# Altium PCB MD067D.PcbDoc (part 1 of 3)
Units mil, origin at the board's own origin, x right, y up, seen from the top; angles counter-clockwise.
Board outline 3650 x 4750 mil, 4 copper layers (Top Layer, GND Layer, Power Layer, Bottom Layer), stack 58.4 mil thick; 234 components, 118 nets, 588 pads, 975 vias.
Unrouted connection lines stored in the file: 45.
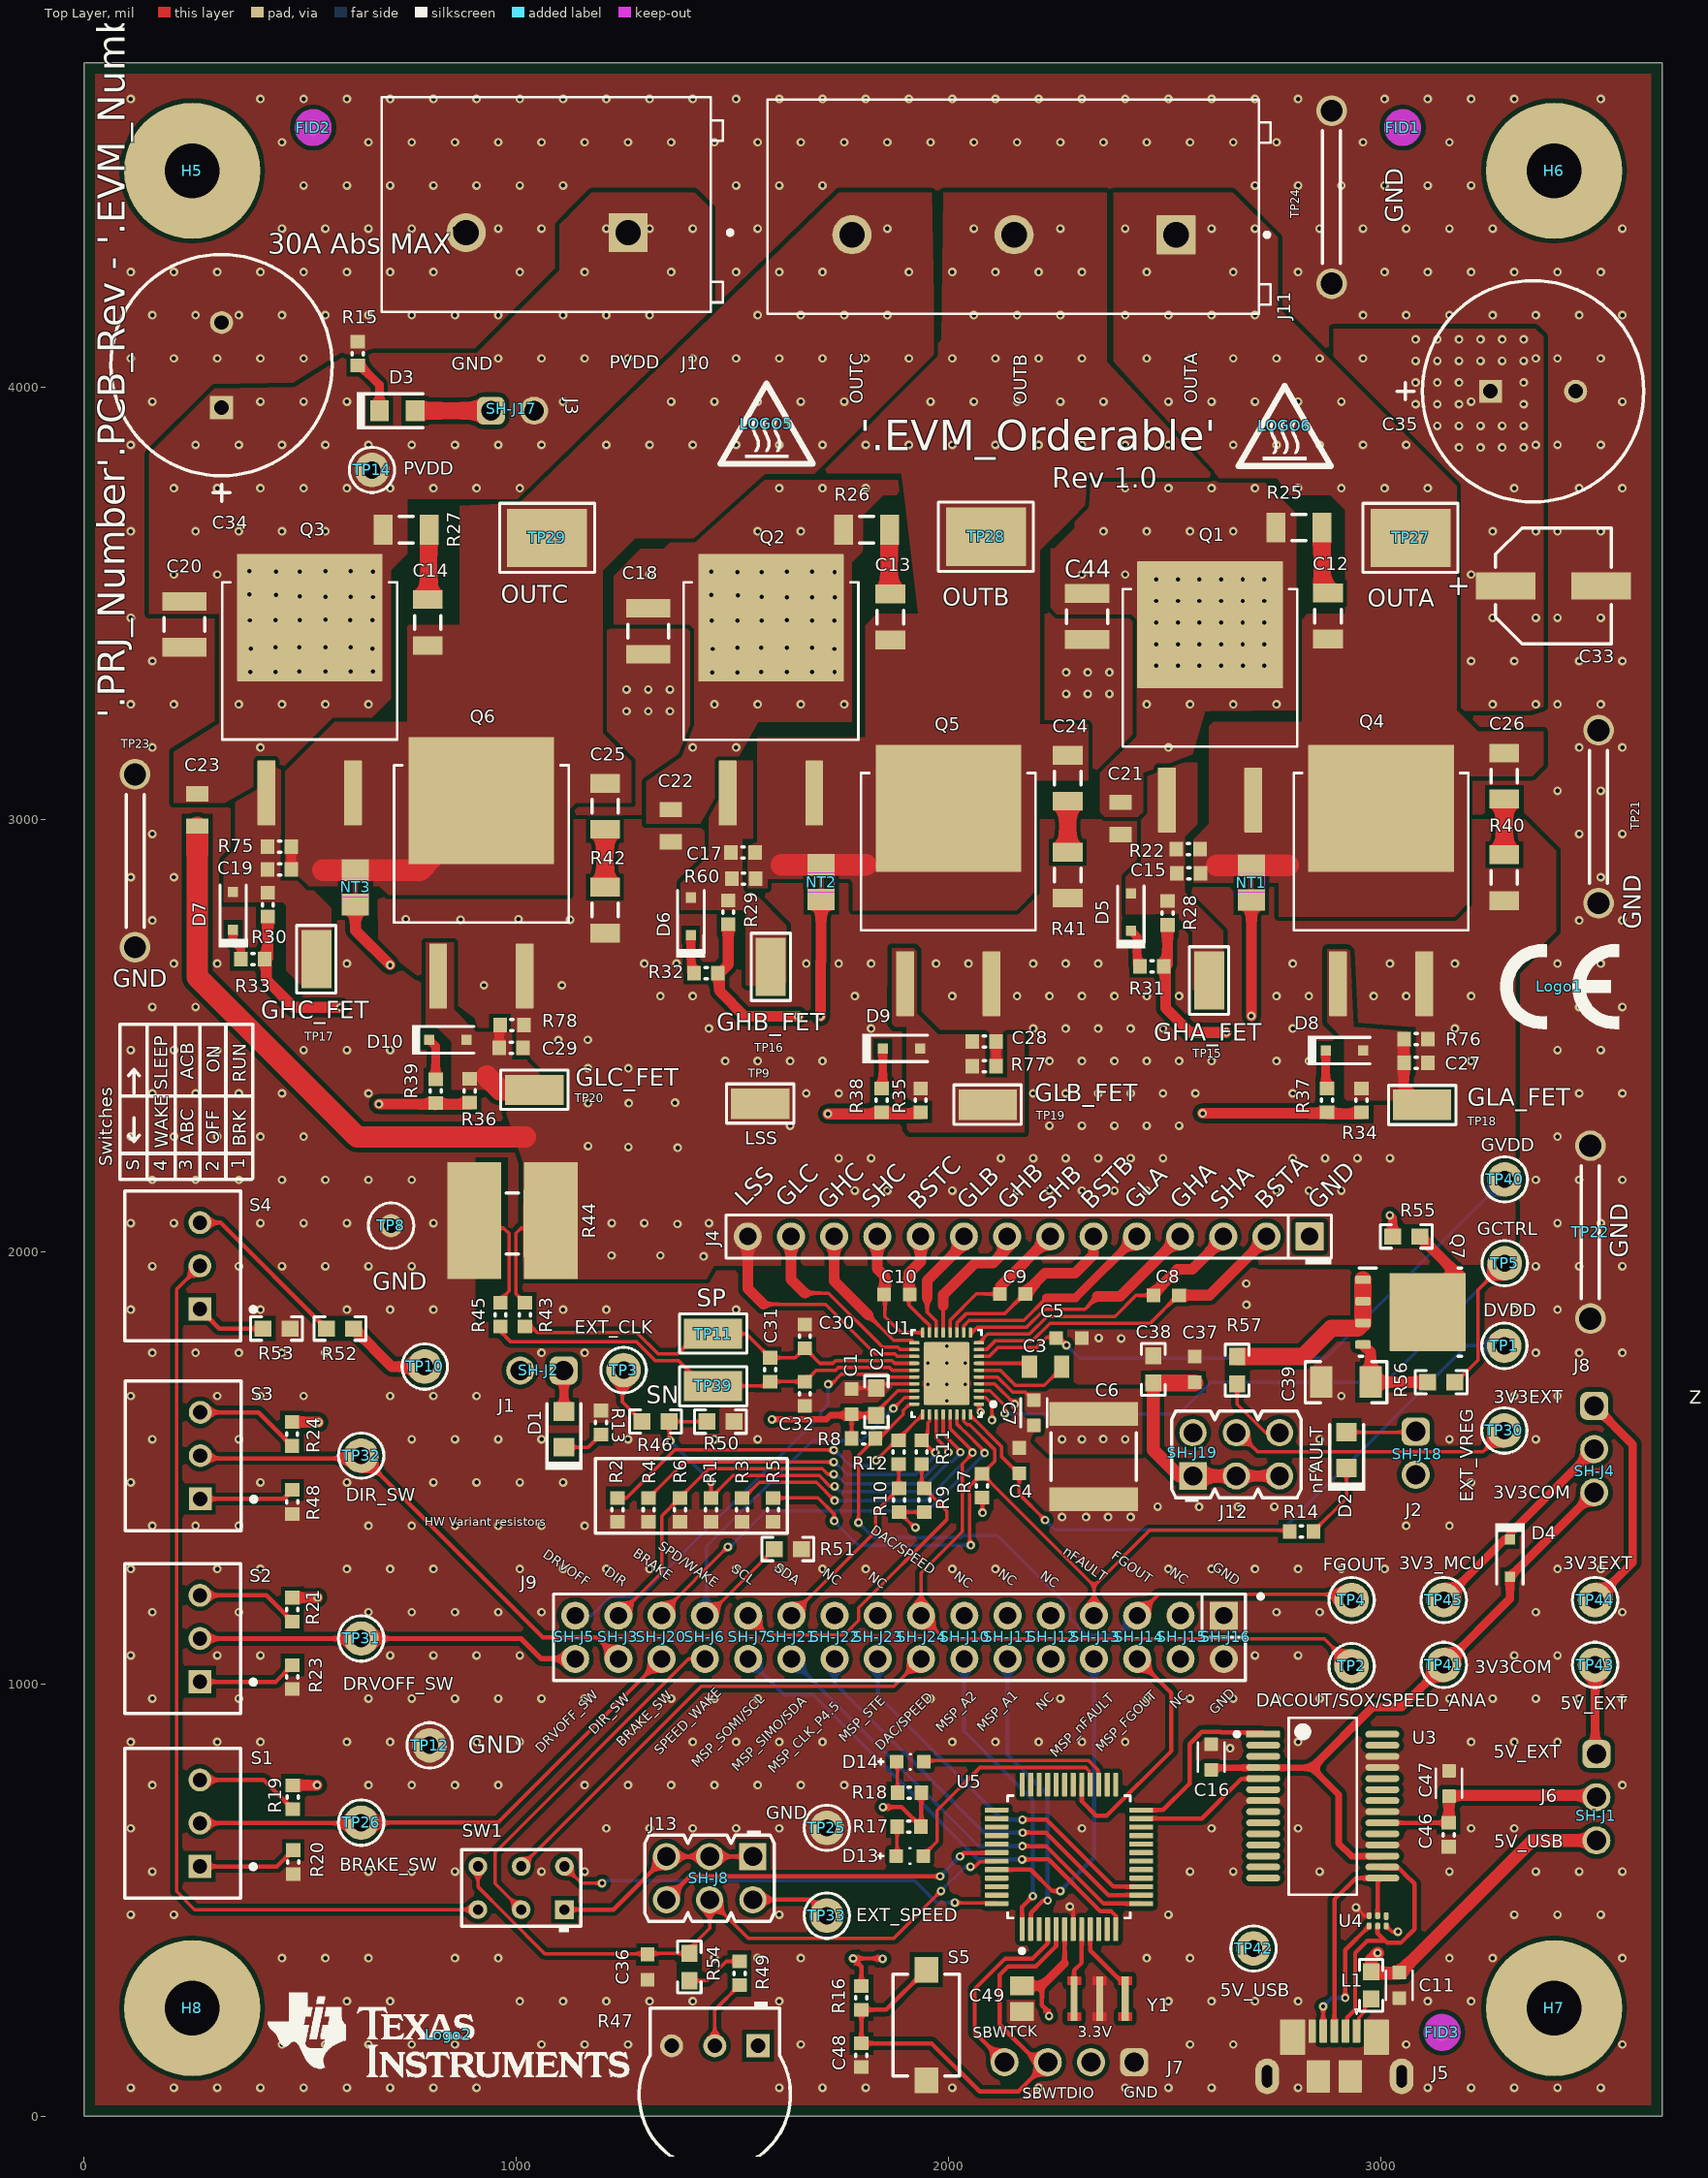
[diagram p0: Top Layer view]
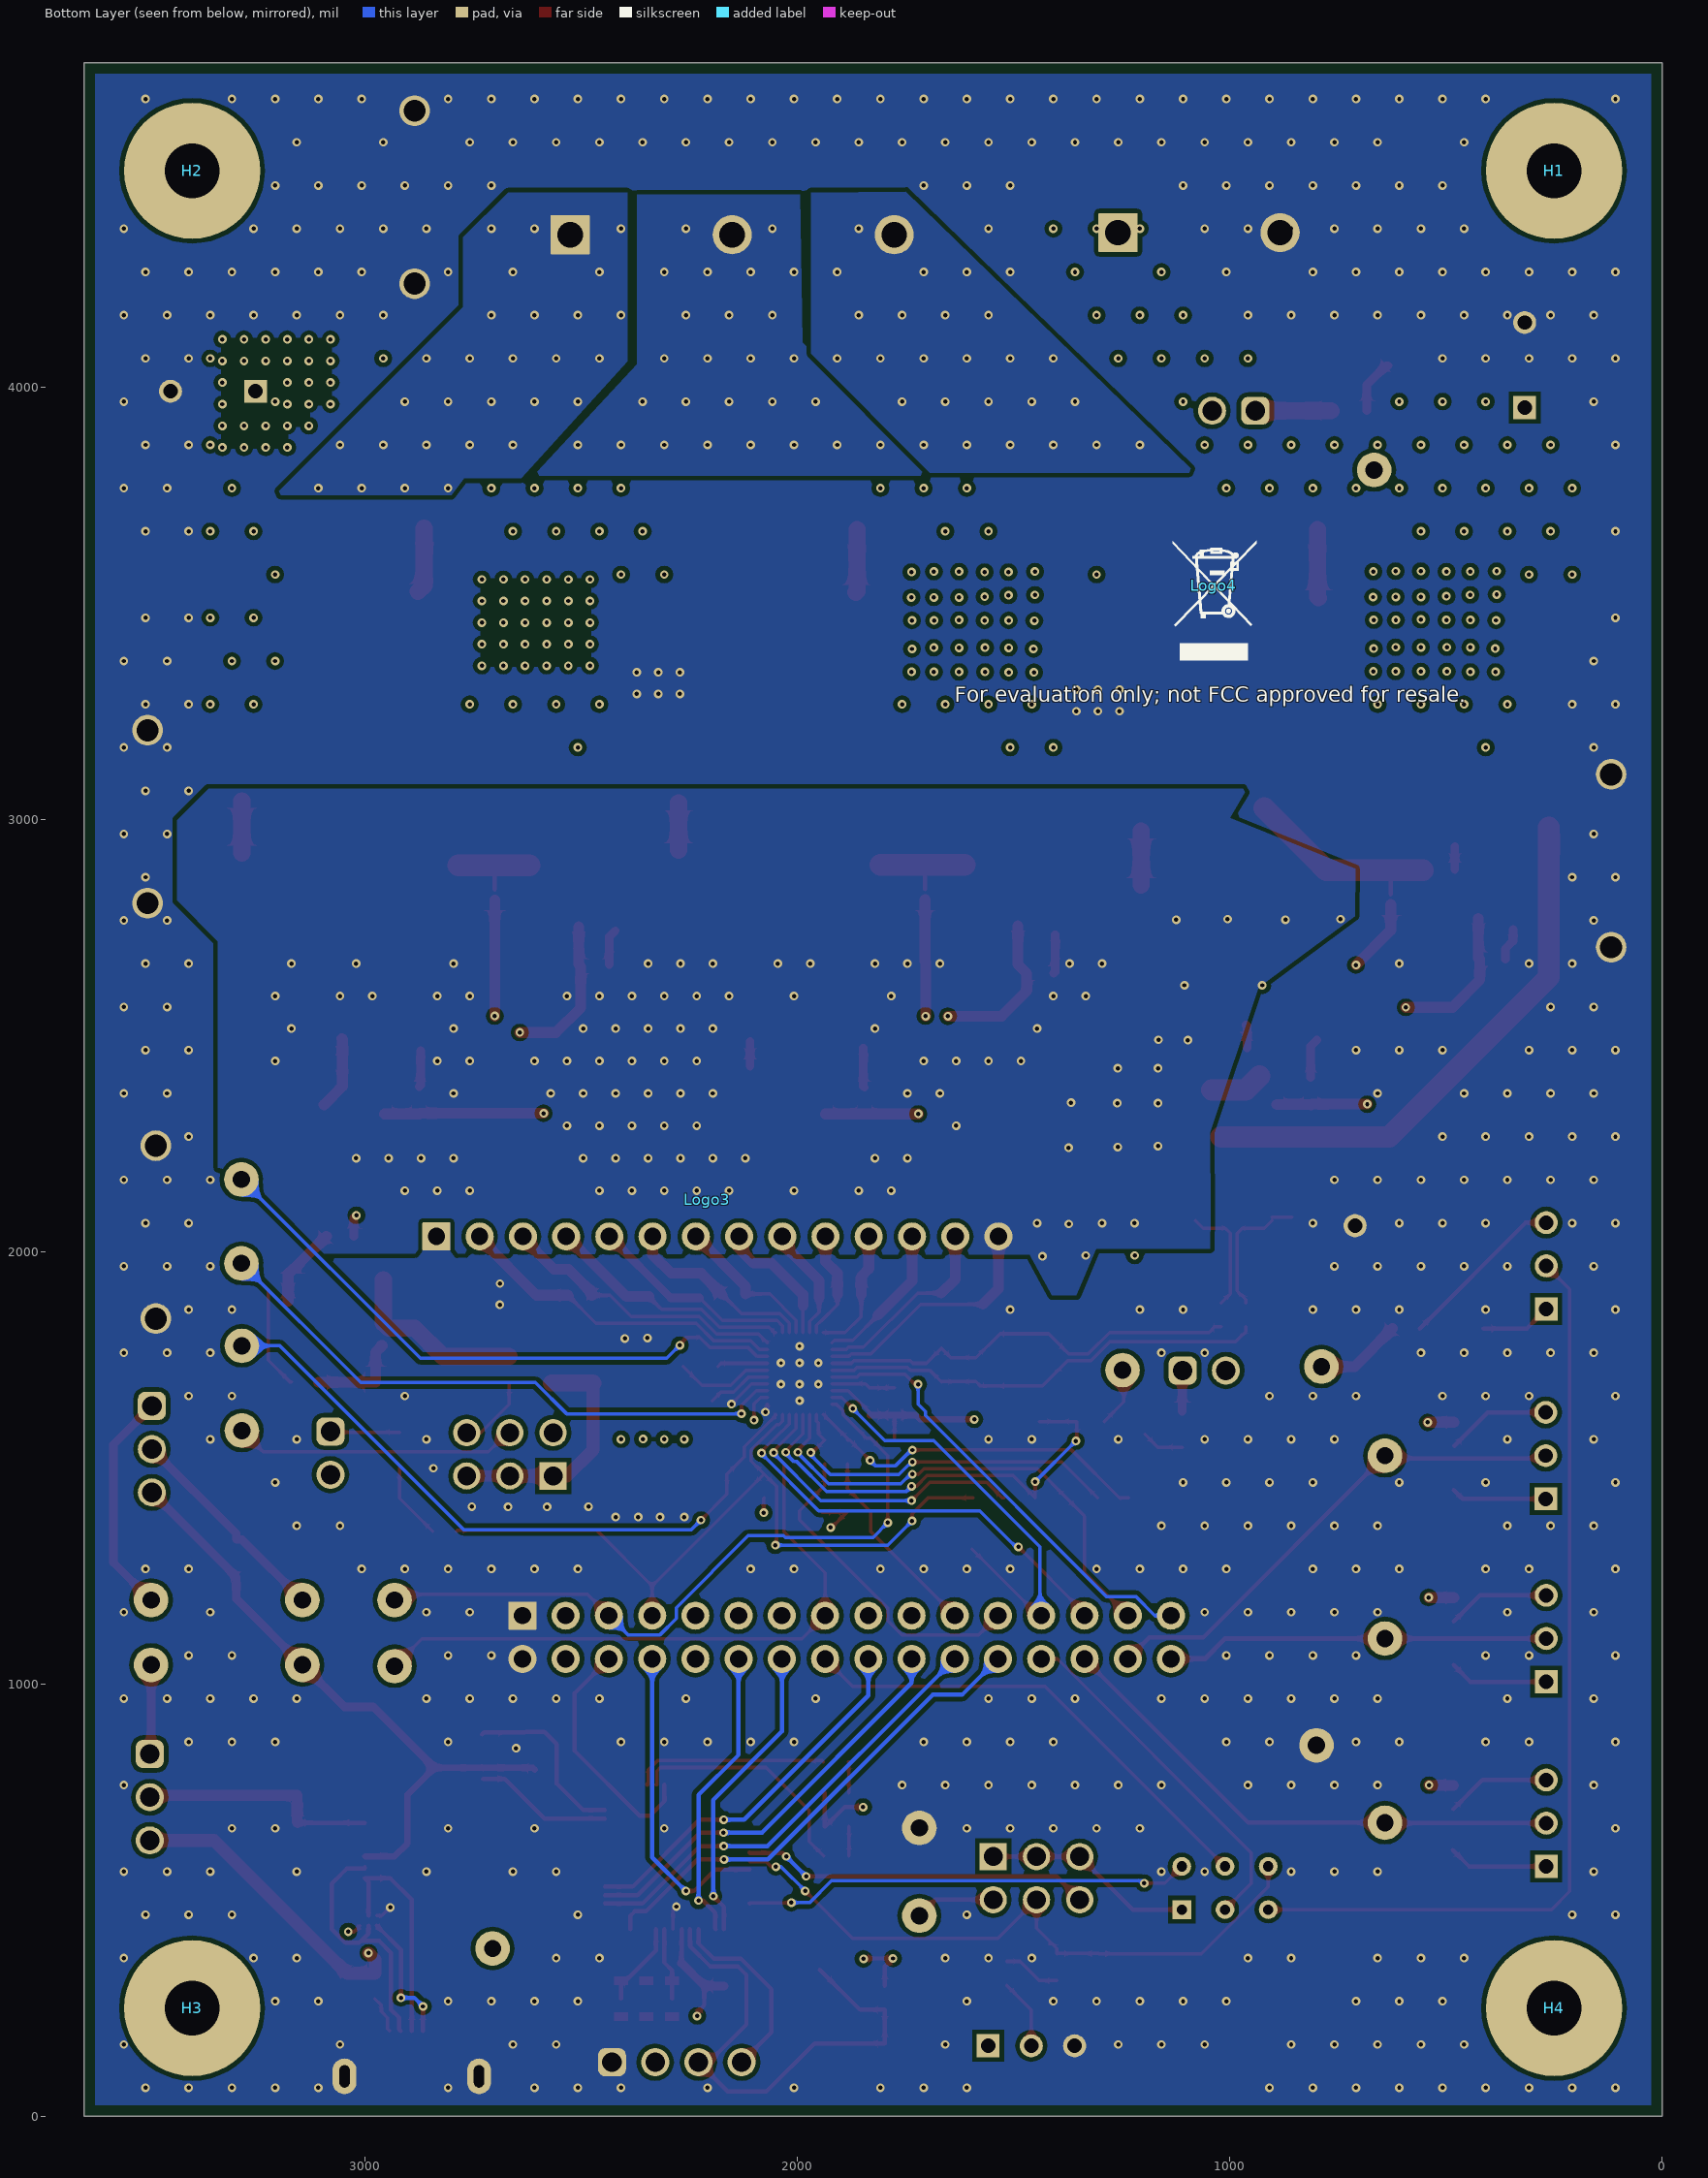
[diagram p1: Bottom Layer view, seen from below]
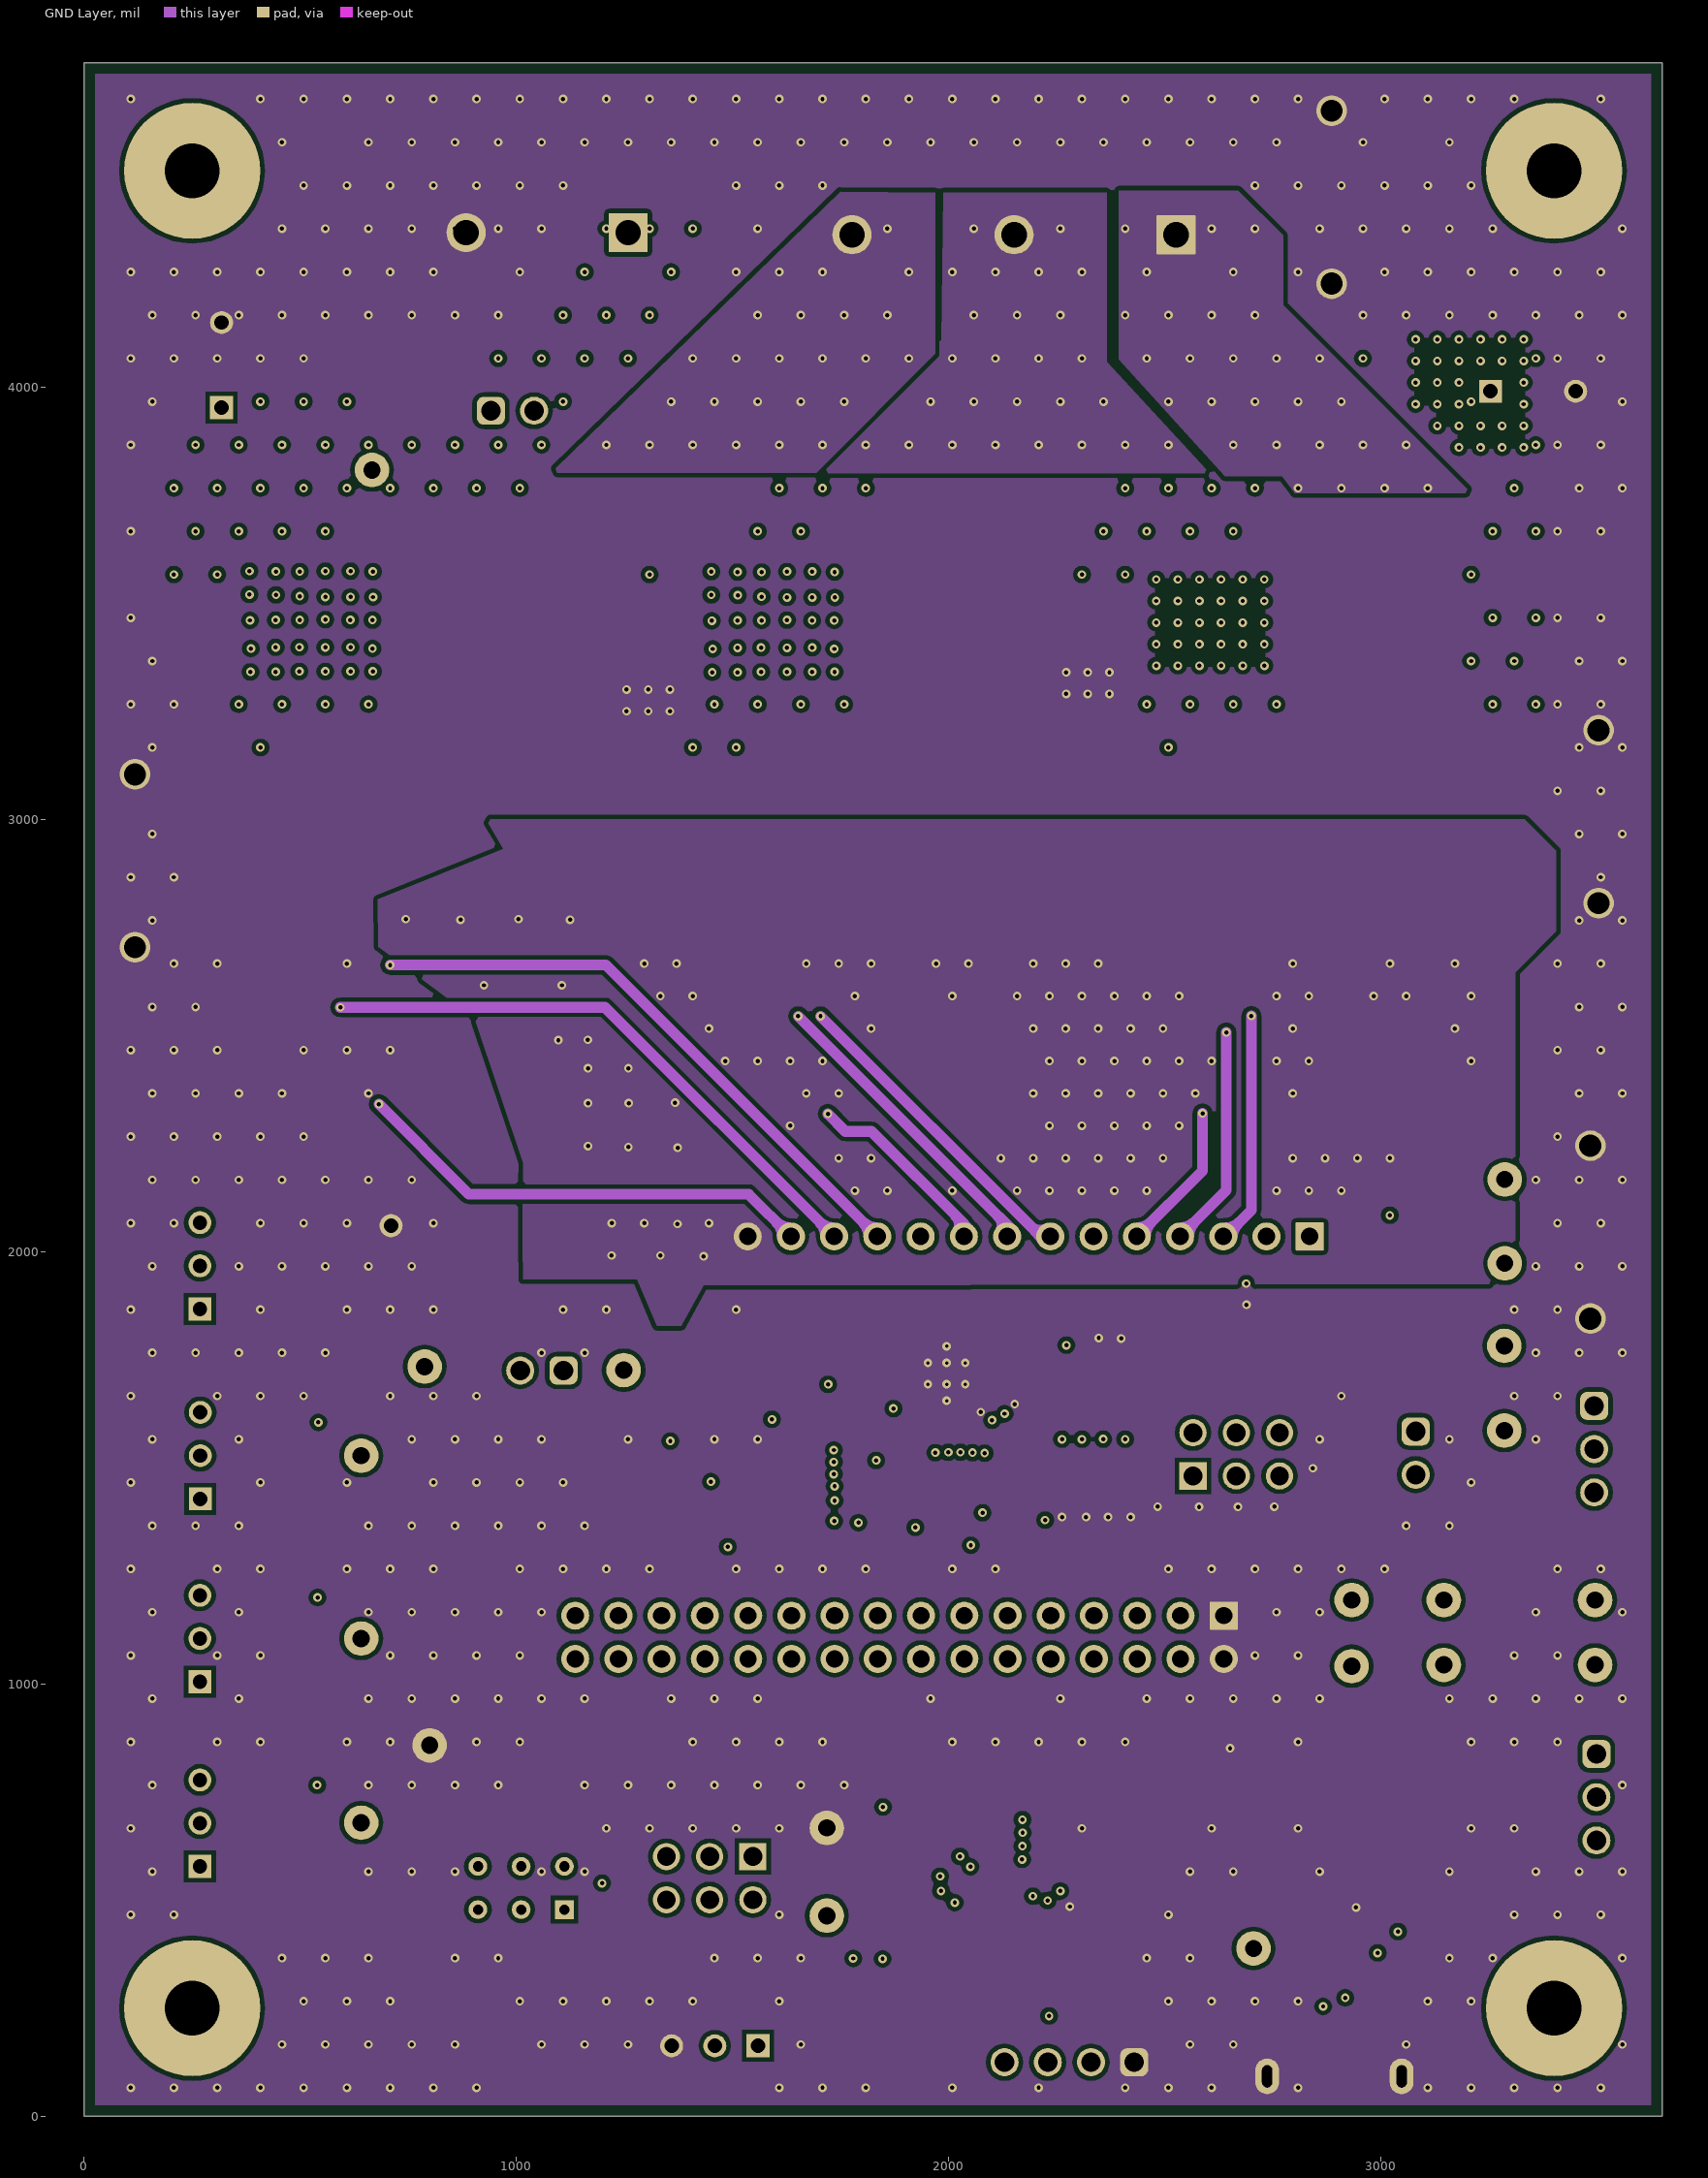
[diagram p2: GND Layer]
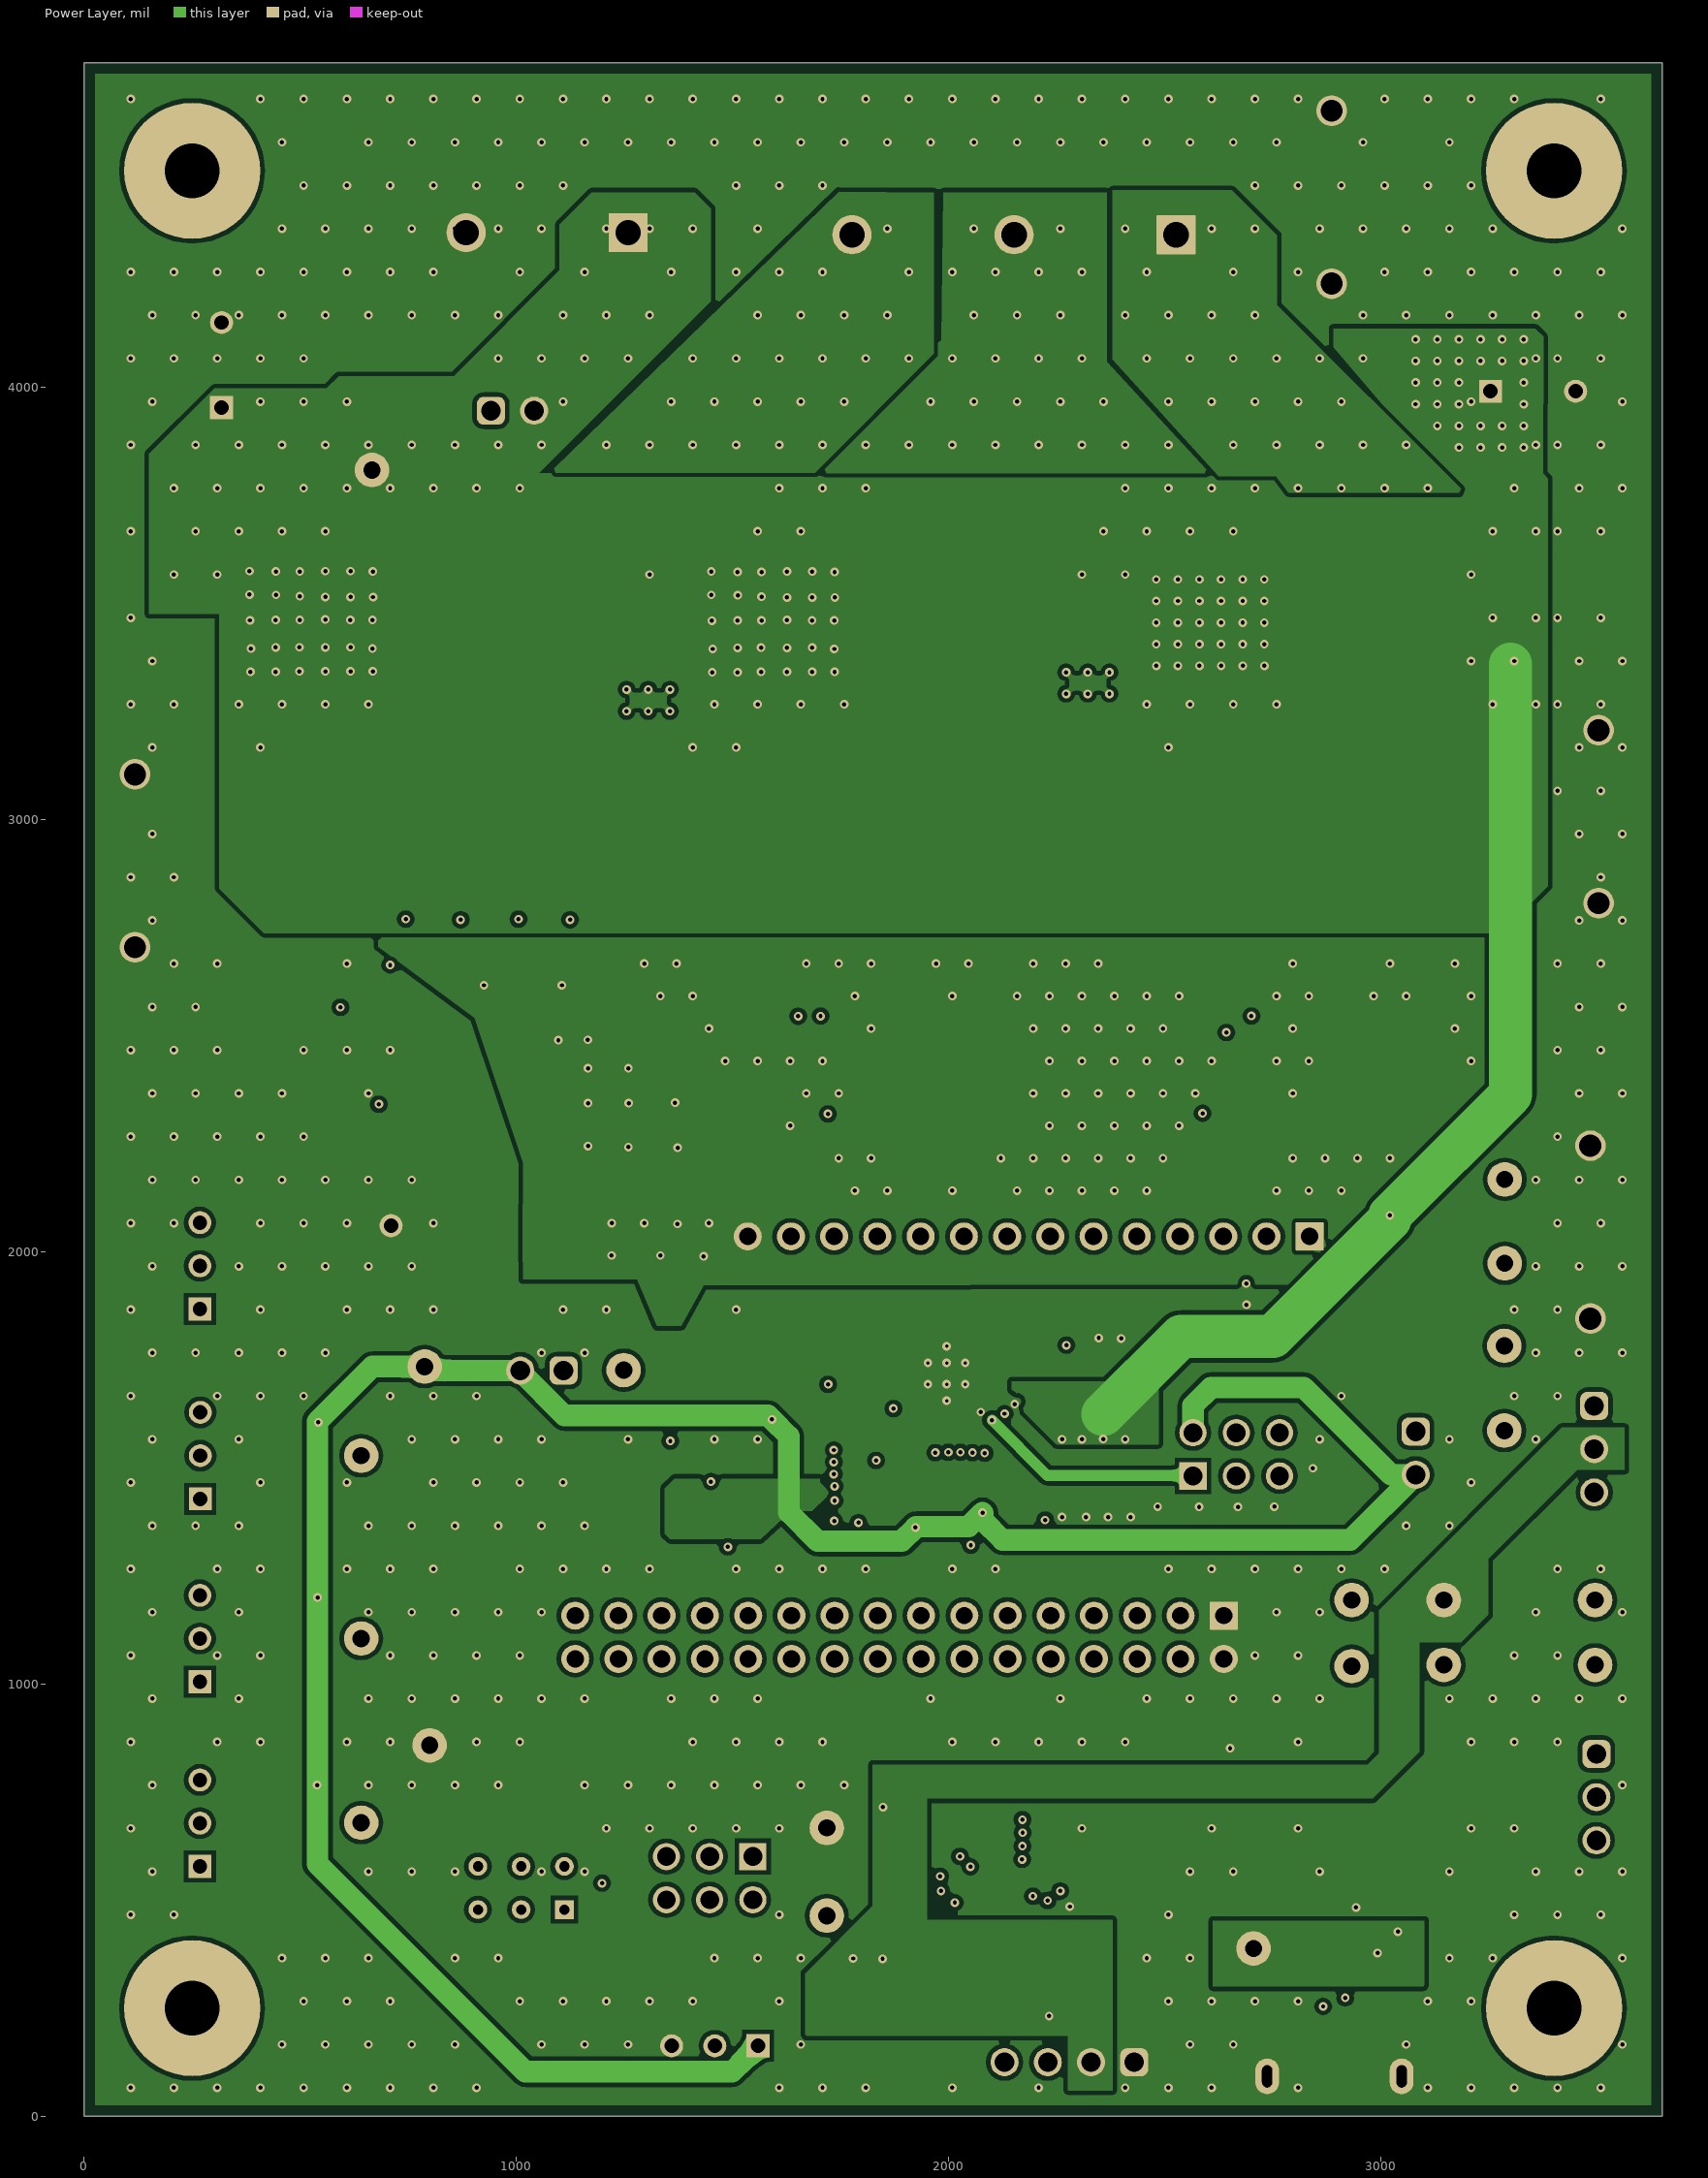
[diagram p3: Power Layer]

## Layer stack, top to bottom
Top Solder: solder mask 0.4, Solder Resist, Dk 3.5
Top Layer: signal copper 2.8
Dielectric 2: core 10, FR-4, Dk 4.8
GND Layer: signal copper 1.4
Dielectric 1: prepreg 30, FR-4, Dk 4.2
Power Layer: signal copper 1.4
Dielectric 3: core 10, FR-4, Dk 4.8
Bottom Layer: signal copper 2.8
Solder Side: solder mask 0.4, Solder Resist, Dk 3.5

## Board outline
0,0 3650,0 3650,4750 0,4750

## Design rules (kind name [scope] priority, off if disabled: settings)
AcuteAngle [All] p1: minimum=4.50000000000000E+0001 checktracksonly=FALSE
AssemblyTestPointUsage [All] p1: valid=2
BoardOutlineClearance BoardOutlineClearance_MountingHoles [OnCopper and InComponentClass('Mounting Holes')] p1: gap=39.37 ignorepadtopadclearanceinfootprint=FALSE
BoardOutlineClearance BoardOutlineClearance_Poly [OnCopper and IsPoly] p2: gap=25 ignorepadtopadclearanceinfootprint=FALSE
BoardOutlineClearance [OnCopper and Not InComponentClass('Logo') and not InComponentClass('FiducialMark') and not InRegion(1000,500,4000,800) and not InPoly] p3: gap=50 ignorepadtopadclearanceinfootprint=FALSE
Clearance Clearance_Keepouts [((IsTrack Or IsArc) And Not InPoly) And IsFree and IsKeepOut vs ((IsTrack Or IsArc) And Not InPoly) And IsFree and IsKeepOut] p1: gap=0 ignorepadtopadclearanceinfootprint=FALSE
Clearance Clearance_Poly [InPolygon] p2: gap=10 ignorepadtopadclearanceinfootprint=TRUE
Clearance Clearance_FiducialMark [IsKeepOut and InComponentClass('FiducialMark') vs IsPad and InComponentClass('FiducialMark')] p3: gap=0 ignorepadtopadclearanceinfootprint=FALSE
Clearance [All] p4: gap=7.87 ignorepadtopadclearanceinfootprint=TRUE
ComponentClearance ComponentClearance_MountingHoles_FiducialMarks [InComponentClass('Mounting Holes') vs InComponentClass('FiducialMark')] p1: gap=50 collisioncheckmode=3 verticalgap=10 showdistances=FALSE
ComponentClearance ComponentClearance_Shunt [InComponentClass('Header') vs InComponentClass('Shunt')] p2: gap=0 collisioncheckmode=3 verticalgap=0 showdistances=FALSE
ComponentClearance ComponentClearance_Logo [InComponentClass('Logo')] p3: gap=20 collisioncheckmode=3 verticalgap=10 showdistances=FALSE
ComponentClearance ComponentClearance_ScrewToNut [HasFootprint('NY PMS 440 0025 PH') vs HasFootprint('Keystone_1902E')] p4: gap=0 collisioncheckmode=3 verticalgap=0 showdistances=FALSE
ComponentClearance ComponentClearance_SmallPassives [HasFootprint('0201*') or HasFootprint('0402*') or HasFootprint('0508') or HasFootprint('0603*') or HasFootprint('0612') or HasFootprint('0805*') or HasFootprint('0815*') or HasFootprint('0830*') or HasFootprint('1206*') or HasFootprint('1210*') or HasFootprint('1808*') or HasFootprint('1812*') or HasFootprint('1825*') or HasFootprint('2010*') or HasFootprint('2220*') or HasFootprint('2225*') or HasFootprint('2512*') or HasFootprint('2728*') or HasFootprint('3518*') vs HasFootprint('0201*') or HasFootprint('0402*') or HasFootprint('0508') or HasFootprint('0603*') or HasFootprint('0612') or HasFootprint('0805*') or HasFootprint('0815*') or HasFootprint('0830*') or HasFootprint('1206*') or HasFootprint('1210*') or HasFootprint('1808*') or HasFootprint('1812*') or HasFootprint('1825*') or HasFootprint('2010*') or HasFootprint('2220*') or HasFootprint('2225*') or HasFootprint('2512*') or HasFootprint('2728*') or HasFootprint('3518*')] p5: gap=14.96 collisioncheckmode=3 verticalgap=10 showdistances=FALSE
ComponentClearance ComponentClearance_THtoSMT [IsThruComponent vs IsSMTComponent] p6: gap=40 collisioncheckmode=3 verticalgap=30 showdistances=FALSE
ComponentClearance ComponentClearance_THtoTH [IsThruComponent vs IsThruComponent] p7: gap=30 collisioncheckmode=3 verticalgap=30 showdistances=FALSE
ComponentClearance [All] p8: gap=0 collisioncheckmode=3 verticalgap=0 showdistances=FALSE
DiffPairsRouting [All] p1: maxlimit=100 minlimit=10 mostfreqgap=10 toplayer_minwidth=15 toplayer_maxwidth=15 toplayer_prefwidth=15 midlayer1_minwidth=15 midlayer1_maxwidth=15 midlayer1_prefwidth=15 midlayer2_minwidth=15 midlayer2_maxwidth=15 midlayer2_prefwidth=15 bottomlayer_minwidth=15 bottomlayer_maxwidth=15 bottomlayer_prefwidth=15 maxuncoupledlength=1000
FabricationTestPointUsage TestPointUsage [All] p1: valid=2 allowmultiple=FALSE
FabricationTestpoint Testpoint [All] p1: side=3 testpointundercomponent=TRUE minsize=40 maxsize=100 preferedsize=60 minholesize=0 maxholesize=40 preferedholesize=32 testpointgrid=1 allowsidetop=TRUE allowsidebottom=TRUE usegrid=TRUE gridtolerance=0.01
FanoutControl Fanout_LCC [IsLCC] p1: bgadir=Out bgaviamode=Centered fanoutstyle=Auto fanoutdirection=Alternating viagrid=1 // Fanout_LCC (Default Rule)
FanoutControl Fanout_BGA [IsBGA] p2: bgadir=Out bgaviamode=Centered fanoutstyle=Auto fanoutdirection=Alternating viagrid=1 // Fanout_BGA (Default Rule)
FanoutControl Fanout_Default [All] p4: bgadir=Out bgaviamode=Centered fanoutstyle=Auto fanoutdirection=Alternating viagrid=1 // Fanout_Default (Default Rule)
FanoutControl Fanout_Small [(CompPinCount < 5)] p5: bgadir=Out bgaviamode=Centered fanoutstyle=Auto fanoutdirection=OutThenIn viagrid=1 // Fanout_Small (Default Rule)
Height [All] p1 off: minheight=0 maxheight=1000 prefheight=500
HoleSize [All] p1: absolutevalues=TRUE maxlimit=250 minlimit=7.87 maxpercent=80.000 minpercent=20.000
HoleToHoleClearance [All] p1: gap=0 allowstackedmicrovias=TRUE
MinimumAnnularRing MinimumAnnularRing_ThermalPadVias [IsVia and InAnyComponent] p1: minimumring=5
MinimumAnnularRing [All] p2: minimumring=5
MinimumSolderMaskSliver MinimumSolderMaskSliver_Logo [InComponentClass('Logo') vs InComponentClass('Logo')] p1: minsoldermaskwidth=0.7
MinimumSolderMaskSliver [All] p2: minsoldermaskwidth=3.94
PlaneConnect [All] p1: planeconnectstyle=Relief reliefexpansion=10 reliefentries=4 reliefconductorwidth=10 reliefairgap=10
PolygonConnect PolygonConnect_1 [All] p1: connectstyle=Direct reliefconductorwidth=10 reliefentries=4 polygonreliefangle="90 Angle" airgapwidth=10
RoutingVias ThermalPadVias [IsVia and InAnyComponent] p1: holewidth=7.87 width=19.68 viastyle="Through Hole" minholewidth=7.87 minwidth=19.68 maxholewidth=12.99 maxwidth=23.62
RoutingVias [All] p2: holewidth=10 width=20 viastyle="Through Hole" minholewidth=10 minwidth=20 maxholewidth=10 maxwidth=20
SilkToBoardRegionClearance [Not ((IsComment or IsDesignator) And (Hide <> 'False')) and not InRegion(1000,500,4000,800)] p1:
SilkToSilkClearance SilkToSilkClearance_Pb-FreeLogo [(HasFootprint('Pb-Free_Overlay_Medium') OR HasFootprint('Pb-Free_Overlay_Small')) vs (HasFootprint('Pb-Free_Overlay_Medium') OR HasFootprint('Pb-Free_Overlay_Small'))] p1: silktosilkclearance=0
SilkToSilkClearance [All] p2: silktosilkclearance=1
SilkToSolderMaskClearance SilkToComponentPadClearance [(IsPad or IsFill or IsRegion) and InAnycomponent] p1: minsilkscreentomaskgap=2 clearancetoexposedcopper=TRUE
SilkToSolderMaskClearance "Silk to Solder Mask Opening" [All] p2: minsilkscreentomaskgap=3.94 clearancetoexposedcopper=FALSE
SolderMaskExpansion [All] p1: expansion=1.97 istentingtop=FALSE
UnRoutedNet [All] p1: checkbadconnections=TRUE
Width [All] p1: maxlimit=100 minlimit=6 preferedwidth=10 checkconnectedcopper=TRUE
12 further rules are at their usual default settings.

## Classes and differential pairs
component class MD067E_INTERFACE: C11 C16 C46 C47 C48 C49 D4 D13 D14 J5 J6 J7 J8 J9 L1 R16 R17 R18 S5 SH-J4 SH-J5 SH-J6 SH-J10 SH-J11 SH-J12 SH-J13 SH-J14 SH-J15 SH-J16 SH-J17 SH-J18 SH-J19 SH-J20 SH-J21 SH-J22 SH-J23 SH-J24 TP41 TP42 TP43 TP44 TP45 U3 U4 U5 Y1
component class Shunt: SH-J1 SH-J2 SH-J3 SH-J4 SH-J5 SH-J6 SH-J7 SH-J8 SH-J10 SH-J11 SH-J12 SH-J13 SH-J14 SH-J15 SH-J16 SH-J17 SH-J18 SH-J19 SH-J20 SH-J21 SH-J22 SH-J23 SH-J24
component class MD067E_POWER_AND_CONNECTORS: C33 C34 C35 C36 C39 GND1 GND2 GND3 J10 J11 J12 J13 Q7 R19 R20 R21 R23 R24 R47 R48 R49 R52 R53 R54 R55 R56 R57 S1 S2 S3 S4 SH-J7 SH-J8 SW1 TP8 TP12 TP21 TP22 TP23 TP24 TP25 TP26 TP27 TP28 TP29 TP30 TP31 TP32 TP33 TP38
component class MD067E_FETS_AND_POWER_STAGE: C12 C13 C14 C15 C17 C18 C19 C20 C21 C22 C23 C24 C25 C26 C27 C28 C29 C30 C31 C32 C44 D5 D6 D7 D8 D9 D10 NT1 NT2 NT3 Q1 Q2 Q3 Q4 Q5 Q6 R22 R25 R26 R27 R28 R29 R30 R31 R32 R33 R34 R35 R36 R37 R38 R39 R40 R41 R42 R43 R44 R45 R60 R75 R76 R77 R78 TP15 TP16 TP17 TP18 TP19 TP20
component class MD067E_DRIVER: '.Part_Label' C1 C2 C3 C4 C5 C6 C7 C8 C9 C10 C37 C38 D1 D2 D3 J1 J2 J3 J4 R1 R2 R3 R4 R5 R6 R7 R8 R9 R10 R11 R12 R13 R14 R15 R46 R50 R51 SH-J1 SH-J2 SH-J3 TP1 TP2 TP3 TP4 TP5 TP9 TP10 TP11 TP14 TP39 TP40 U1
component class Header: J1 J2 J3 J4 J6 J7 J8 J9 J12 J13
component class "Mounting Holes": H5 H6 H7 H8
component class Logo: Logo2
component class MD067E_HARDWARE: FID1 FID2 FID3 H1 H2 H3 H4 H5 H6 H7 H8 Logo1 Logo2 Logo3 Logo4 LOGO5 LOGO6 ZZ1 ZZ2 ZZ3 ZZ4
component class FiducialMark: FID1 FID2 FID3
component class AssemblyNote: ZZ1 ZZ2 ZZ3 ZZ4

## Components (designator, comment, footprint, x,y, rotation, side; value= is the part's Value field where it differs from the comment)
C1 "885012106006" WCAP-CSGP_0603_L1.6W0.8H0.8_Reflow 1775,1653 r270 top value=10uF
C2 "885012206020" 0603 1832.49,1653 r270 top value=0.1uF
C3 "885012207130" WCAP-CSGP_0805_L2W1.25H1.25 2224,1734 r180 top value=470nF
C4 "885012106003" WCAP-CSGP_0603_L1.6W0.8H0.8_Reflow 2163,1516.46 r270 top value=1uF
C5 "885012106031" WCAP-CSGP_0603_L1.6W0.8H0.8_Reflow 2278,1800 r180 top value=10uF
C6 "22201C106MAT2A" 2220_280L 2335,1526 r270 top value=10uF
C7 "885012206120" FP-885012206120_0603-MFG 2197,1627.28 r90 top value=100nF
C8 "885012106022" WCAP-CSGP_0603_L1.6W0.8H0.8_Reflow 2503,1899 r180 top value=1uF
C9 "885012106022" WCAP-CSGP_0603_L1.6W0.8H0.8_Reflow 2147.56,1902.13 r0 top value=1uF
C10 "885012106022" WCAP-CSGP_0603_L1.6W0.8H0.8_Reflow 1880,1901 r0 top value=1uF
C11 "885012206120" FP-885012206120_0603-MFG 3042,303 r90 top value=100nF
C12 "12061C392KAZ2A" 1206L 2877.09,3470 r90 top value=3900pF
C13 "12061C392KAZ2A" 1206L 1865,3467.91 r90 top value=3900pF
C14 "12061C392KAZ2A" 1206L 795,3455 r90 top value=3900pF
C15 "GRM188R71H202KA01D" 0603L 2555,2874.88 r0 top value=2000pF
C16 "885012206120" FP-885012206120_0603-MFG 2607,831 r270 top value=100nF
C17 "GRM188R71H202KA01D" 0603L 1524.12,2923 r0 top value=2000pF
C18 "GRM32DC72A475KE01L" 1210_220L 1305,3435 r270 top value=4.7uF
C19 "GRM188R71H202KA01D" 0603L 452,2884 r0 top value=2000pF
C20 "GRM32DC72A475KE01L" 1210_220L 232.32,3450.75 r270 top value=4.7uF
C21 "885012207122" WCAP-CSGP_0805_L2W1.25H0.8_Reflow 2397.68,3001.97 r90 top value=0.01uF
C22 "885012207122" WCAP-CSGP_0805_L2W1.25H0.8_Reflow 1356.8,2985 r90 top value=0.01uF
C23 "885012207122" WCAP-CSGP_0805_L2W1.25H0.8_Reflow 261.85,3021.65 r90 top value=0.01uF
C24 "12061C392KAZ2A" 1206L 2275,3095 r270 top value=3900pF
C25 "12061C392KAZ2A" 1206L 1205,3030 r270 top value=3900pF
C26 "12061C392KAZ2A" 1206L 3285,3100 r270 top value=3900pF
C27 "GRM188R71H202KA01D" 0603L 3081,2437 r0 top value=2000pF
C28 "GRM188R71H202KA01D" 0603L 2082,2486 r0 top value=2000pF
C29 "GRM188R71H202KA01D" 0603L 988,2471 r0 top value=2000pF
C30 "06031C331KAT2A" 0603L 1667,1804 r270 top value=330pF
C31 "C1608NP01H103J080AA" 0603L 1587,1727 r270 top value=0.01uF
C32 "06031C331KAT2A" 0603L 1667,1671 r270 top value=330pF
C33 "865081745005" WCAP-ASLI_D6.3H7.7 3398.7,3540 r180 top value=10uF
C34 "EKYB101ELL391MK35S" KYB_1250x3500 318,4050.57 r90 top value=390uF
C35 "EKYB101ELL391MK35S" KYB_1250x3500 3351.57,3990 r0 top value=390uF
C36 "885012206003" WCAP-CSGP_0603_L1.6W0.8H0.8_Reflow 1303.24,345 r270 top value=100pF
C37 "885012106006" WCAP-CSGP_0603_L1.6W0.8H0.8_Reflow 2569,1727.61 r270 top value=10uF
C38 "885012206020" 0603 2473,1727.61 r90 top value=0.1uF
C39 "12065A202JAT2A" 1206 2918.82,1698 r180 top value=2000pF
C44 "GRM32DC72A475KE01L" 1210_220L 2320,3469 r270 top value=4.7uF
C46 "GRM188Z71A475ME15D" 0603L 3156,651 r90 top value=4.7uF
C47 "885012206120" FP-885012206120_0603-MFG 3157,769.72 r270 top value=100nF
C48 "885012206034" 0603L 1798,141 r270 top value=1000pF
C49 "885012207103" 0805L 2168.94,272 r270 top value=1uF
D1 "150080VS75000" WL-SMCW_Green_0805 1110,1589 r90 top value="Bright Green"
D2 "150080RS75000" WL-SMCW_RED_0805 2920,1541 r90 top value=Red
D3 "150080VS75000" WL-SMCW_Green_0805 724.65,3945 r0 top value="Bright Green"
D4 "BAT165E6327HTSA1" SOD-323 3298,1291 r270 top value=40V
D5 "1N4448WX-TP" SOD-323 2421.3,2785.43 r90 top value=75V
D6 "1N4448WX-TP" SOD-323 1403.58,2775.59 r90 top value=75V
D7 "1N4448WX-TP" SOD-323 344.69,2788 r90 top value=75V
D8 "1N4448WX-TP" SOD-323 2915,2465 r0 top value=75V
D9 "1N4448WX-TP" SOD-323 1890.8,2470 r0 top value=75V
D10 "1N4448WX-TP" SOD-323 841.57,2489.83 r0 top value=75V
D13 "150060RS75003" FP-150060RS75003_0603-MFG 1910,602.05 r0 top value=Red
D14 "150060RS75003" FP-150060RS75003_0603-MFG 1911,820 r0 top value=Red
FID1 "Fiducial" Fiducial10-20 3050,4600 r0 top
FID2 "Fiducial" Fiducial10-20 530,4600 r0 top
FID3 "Fiducial" Fiducial10-20 3141,194 r0 top
H1 "1902E" Keystone_1902E 250.36,4500 r180 bottom
H2 "1902E" Keystone_1902E 3400.36,4500 r180 bottom
H3 "1902E" Keystone_1902E 3400.36,250 r180 bottom
H4 "1902E" Keystone_1902E 250.36,250 r180 bottom
H5 "NY PMS 440 0025 PH" "NY PMS 440 0025 PH" 250,4500 r0 top
H6 "NY PMS 440 0025 PH" "NY PMS 440 0025 PH" 3400,4500 r0 top
H7 "NY PMS 440 0025 PH" "NY PMS 440 0025 PH" 3400,250 r0 top
H8 "NY PMS 440 0025 PH" "NY PMS 440 0025 PH" 250,250 r0 top
J1 "61300211121" WURTH_61300211121 1059,1725 r180 top
J2 "61300211121" WURTH_61300211121 3080,1534 r270 top
J3 "61300211121" WURTH_61300211121 991,3945 r0 top
J4 "TSW-114-07-G-S" TSW-114-07-G-S 2185,2035 r180 top
J5 "1051640001" Molex_1051640001 2892,35.19 r0 top
J6 "61300311121" WURTH_61300311121 3498,738 r270 top
J7 "61300411121" WURTH_61300411121 2279,125 r180 top
J8 "61300311121" WURTH_61300311121 3493,1543 r270 top
J9 "TSW-116-07-G-D" TSW-116-07-G-D 1886,1108 r180 top
J10 "691250910002" FP-691250910002_CONN_TERM_BLK2-MFG 1071,4422 r180 top
J11 "691250910003" FP-691250910003_CONN_TERM_BLK3-MFG 2151,4417 r180 top
J12 "61300621121" Wurth_61300621121 2665,1531 r90 top
J13 "Header_3x2" Wurth_61300621121 1447,550.79 r270 top
L1 "74279228111" 0603 2977,303 r270 top value="110 ohm"
Logo1 "CE Mark" CE_Mark_5mm 3413,2613 r0 top
Logo2 "Texas Instruments" TI_Stacked_Overlay_Small 843,188 r0 top
Logo3 "FCC disclaimer" FCC_disclaimer 2208,2120 r180 bottom
Logo4 "WEEE logo" WEEE_Minimum 1037,3540 r180 bottom
LOGO5 "CAUTION HOT SURFACE" IEC_HotSurface_Small 1578.78,3915.26 r0 top
LOGO6 "CAUTION HOT SURFACE" IEC_HotSurface_Small 2776.96,3910.14 r0 top
NT1 "Net-Tie" Net-Tie_0805_HV_NoOverlay 2700,2853.5 r90 top net-tie
NT2 "Net-Tie" Net-Tie_0805_HV_NoOverlay 1704.76,2854.33 r90 top net-tie
NT3 "Net-Tie" Net-Tie_0805_HV_NoOverlay 627.77,2842.52 r90 top net-tie
Q1 "CSD18536KTTT" KTT0002A-MFG#1 2604.37,3350 r0 top
Q2 "CSD18536KTTT" KTT0002A-MFG#2 1589,3366 r0 top
Q3 "CSD18536KTTT" KTT0002A-MFG#1 521.92,3366.31 r0 top
Q4 "CSD18536KTTT" KTT0002A-MFG#1 3000,2925 r0 top
Q5 "CSD18536KTTT" KTT0002A-MFG#1 1999.05,2925 r0 top
Q6 "CSD18536KTTT" KTT0002A-MFG#1 919,2943 r0 top
Q7 "CSD18534Q5A" DQJ0008A 3068.04,1860 r0 top value=60V
R1 "ERJ-3GEY0R00V" 0603L 1450,1402.8 r270 top value=0
R2 "ERJ-3GEY0R00V" 0603L 1234,1402.8 r270 top value=0
R3 "ERJ-3GEY0R00V" 0603L 1522,1402.8 r270 top value=0
R4 "ERJ-3GEY0R00V" 0603L 1306,1402.8 r270 top value=0
R5 "ERJ-3GEY0R00V" 0603L 1594,1402.8 r270 top value=0
R6 "ERJ-3GEY0R00V" 0603L 1378,1402.8 r270 top value=0
R7 "CRCW06035K10JNEA" 0603L 2077,1458.27 r90 top value=5.1k
R8 "CRCW06035K10JNEA" 0603L 1803,1568 r180 top value=5.1k
R9 "CRCW06035K10JNEA" 0603L 1943,1425 r270 top value=5.1k
R10 "CRCW06035K10JNEA" 0603L 1885,1425 r270 top value=5.1k
R11 "ERJ-3GEY0R00V" 0603L 1937.29,1536.29 r90 top value=0
R12 "ERJ-3GEY0R00V" 0603L 1884.29,1536.29 r90 top value=0
R13 "RC0603JR-07820RL" 0603L 1196,1604.72 r270 top value=820
R14 "RC0603JR-07820RL" 0603L 2816,1353 r0 top value=820
R15 "RG1608P-202-B-T5" 0603L 633,4077 r270 top value=2.00k
R16 "RC0603JR-0747KL" 0603L 1798,274 r90 top value=47k
R17 "RC0603JR-07470RL" 0603L 1908,670 r0 top value=470
R18 "RC0603JR-07470RL" 0603L 1909,748 r0 top value=470
R19 "ERA-3ARW103V" 0603L 483,738 r90 top value=10.0k
R20 "ERA-3ARW103V" 0603L 484,588 r90 top value=10.0k
R21 "ERA-3ARW103V" 0603L 482,1172 r90 top value=10.0k
R22 "CRCW060310K0JNEA" 0603L 2554,2931 r180 top value=10k
R23 "ERA-3ARW103V" 0603L 482,1016 r90 top value=10.0k
R24 "ERA-3ARW103V" 0603L 481,1578 r90 top value=10.0k
R25 "CRCW12061R50FKEA" 1206L 2810,3675 r0 top value=1.50
R26 "CRCW12061R50FKEA" 1206L 1810,3670 r0 top value=1.50
R27 "CRCW12061R50FKEA" 1206L 745,3670 r0 top value=1.50
R28 "CRCW060310R0JNEA" 0603L 2505.94,2783.19 r90 top value=10
R29 "CRCW060310R0JNEA" 0603L 1490,2785 r90 top value=10
R30 "CRCW060310R0JNEA" 0603L 425,2802.52 r90 top value=10
R31 "CRCW060310R0JNEA" 0603L 2470,2660 r180 top value=10
R32 "CRCW060310R0JNEA" 0603L 1438.45,2644.13 r180 top value=10
R33 "CRCW060310R0JNEA" 0603L 390.42,2676.39 r180 top value=10
R34 "CRCW060310R0JNEA" 0603L 2955,2350 r90 top value=10
R35 "CRCW060310R0JNEA" 0603L 1935,2350 r90 top value=10
R36 "CRCW060310R0JNEA" 0603L 891.77,2372.05 r90 top value=10
R37 "CRCW060310R0JNEA" 0603L 2875,2350 r90 top value=10
R38 "CRCW060310R0JNEA" 0603L 1845,2350 r90 top value=10
R39 "CRCW060310R0JNEA" 0603L 813.03,2371.12 r90 top value=10
R40 "CRCW12061R50FKEA" 1206L 3285,2865 r90 top value=1.50
R41 "CRCW12061R50FKEA" 1206L 2275,2870.88 r90 top value=1.50
R42 "CRCW12061R50FKEA" 1206L 1205,2790 r90 top value=1.50
R43 "ERJ-3GEY0R00V" 0603L 1020,1854 r90 top value=0
R44 "CRE2512-FZ-R001E-3" CRE2512-R1_R4 990.71,2065.3 r0 top value=0.001
R45 "ERJ-3GEY0R00V" 0603L 963,1854 r90 top value=0
R46 "ERJ-3GEY0R00V" 0603 1322,1607 r0 top value=0
R47 "3352T-1-253LF" Bourns_3352T 1459,163 r180 top value="25 kohm"
R48 "ERA-3ARW103V" 0603L 482,1421 r90 top value=10.0k
R49 "ERJ-3GEY0R00V" 0603L 1516,330.73 r270 top value=0
R50 "RMCF0603FG1M00" 0603 1472,1607 r180 top value=1.00Meg
R51 "RT0603BRD07100KL" 0603 1628,1312 r180 top value=100k
R52 "ERA-3ARW103V" 0603 592,1822 r0 top value=10.0k
R53 "ERA-3ARW103V" 0603 445,1822 r180 top value=10.0k
R54 "RT0603BRD0747RL" 0603 1400,345 r270 top value=47.0
R55 "ERJ-3GEY0R00V" 0603 3058,2035 r180 top value=0
R56 "ERJ-3GEY0R00V" 0603 3139,1698 r180 top value=0
R57 "ERJ-3GEY0R00V" 0603 2667,1725.87 r270 top value=0
R60 "CRCW060310K0JNEA" 0603L 1525.59,2863 r180 top value=10k
R75 "CRCW060310K0JNEA" 0603L 452,2937 r180 top value=10k
R76 "CRCW060310K0JNEA" 0603L 3081,2492 r180 top value=10k
R77 "CRCW060310K0JNEA" 0603L 2082,2429 r180 top value=10k
R78 "CRCW060310K0JNEA" 0603L 989.82,2523.99 r180 top value=10k
S1 "SW_SPDT_COM2_1_3" SW_B12AP 228.63,677.95 r180 top
S2 "SW_SPDT_COM2_1_3" SW_B12AP 228.63,1105 r180 top
S3 "SW_SPDT_COM2_1_3" SW_B12AP 229.63,1528 r180 top
S4 "B12AP" SW_B12AP 228.63,1967 r180 top
S5 "SW_SPST-single" SW_434121025816 1948,211 r270 top
SH-J1 "60900213421" Wurth_60900213421 3498,695.15 r90 top value=1x2
SH-J2 "60900213421" Wurth_60900213421 1051.85,1725 r0 top value=1x2
SH-J3 "60900213421" Wurth_60900213421 1235.4,1109 r90 top value=1x2
SH-J4 "60900213421" Wurth_60900213421 3494,1492 r90 top value=1x2
SH-J5 "60900213421" Wurth_60900213421 1135,1109 r90 top value=1x2
SH-J6 "60900213421" Wurth_60900213421 1436.2,1109 r90 top value=1x2
SH-J7 "60900213421" Wurth_60900213421 1536.6,1109 r90 top value=1x2
SH-J8 "60900213421" Wurth_60900213421 1445,550 r270 top value=1x2
SH-J10 "60900213421" Wurth_60900213421 2038.6,1109 r90 top value=1x2
SH-J11 "60900213421" Wurth_60900213421 2139,1109 r90 top value=1x2
SH-J12 "60900213421" Wurth_60900213421 2239.4,1109 r90 top value=1x2
SH-J13 "60900213421" Wurth_60900213421 2339.8,1109 r90 top value=1x2
SH-J14 "60900213421" Wurth_60900213421 2440.2,1109 r90 top value=1x2
SH-J15 "60900213421" Wurth_60900213421 2540.6,1109 r90 top value=1x2
SH-J16 "60900213421" Wurth_60900213421 2641,1109 r90 top value=1x2
SH-J17 "60900213421" Wurth_60900213421 989,3949 r180 top value=1x2
SH-J18 "60900213421" Wurth_60900213421 3084,1531.12 r90 top value=1x2
SH-J19 "60900213421" Wurth_60900213421 2564.06,1535 r90 top value=1x2
SH-J20 "60900213421" Wurth_60900213421 1335.8,1109 r90 top value=1x2
SH-J21 "60900213421" Wurth_60900213421 1637,1109 r90 top value=1x2
SH-J22 "60900213421" Wurth_60900213421 1737.4,1109 r90 top value=1x2
SH-J23 "60900213421" Wurth_60900213421 1837.8,1109 r90 top value=1x2
SH-J24 "60900213421" Wurth_60900213421 1938.2,1109 r90 top value=1x2
SW1 "G22AP" SW_G2xAP 1011,528 r180 top
TP1 "DVDD" Keystone5000 3285,1782 r0 top
TP2 "DACOUT/SOX/SPEED_ANA" Keystone5002 2931.82,1041 r0 top
TP3 "EXT_CLK" Keystone5002 1248,1725.87 r180 top
TP4 "FGOUT" Keystone5002 2931.82,1194 r0 top
TP5 "GCTRL" Keystone5002 3286,1973 r90 top
TP8 "GND" Keystone5001#1 710.07,2060 r90 top
TP9 "LSS" Testpoint_Keystone_Miniature 1564,2342 r180 top
TP10 "AVDD" Keystone5000 788,1734 r0 top
TP11 "SP" Testpoint_Keystone_Miniature 1454.87,1810 r180 top
TP12 "GND" Keystone5001#2 799.38,858 r0 top
TP14 "PVDD" Keystone5000 666,3808 r90 top
TP15 "GHA_FET" Testpoint_Keystone_Miniature 2602.4,2627.01 r270 top
TP16 "GHB_FET" Testpoint_Keystone_Miniature 1588.09,2658.66 r90 top
TP17 "GHC_FET" Testpoint_Keystone_Miniature 537.44,2676.39 r270 top
TP18 "GLA_FET" Testpoint_Keystone_Miniature 3095,2339.62 r0 top
TP19 "GLB_FET" Testpoint_Keystone_Miniature 2090,2339.62 r180 top
TP20 "GLC_FET" Testpoint_Keystone_Miniature 1041.38,2374.02 r180 top
TP21 "GND" Harwin_D3082-05 3503,3006 r90 top
TP22 "GND" Harwin_D3082-05 3484,2045 r270 top
TP23 "GND" Harwin_D3082-05 118,2904 r270 top
TP24 "GND" Harwin_D3082-05 2885.54,4439 r270 top
TP25 "GND" Keystone5001#2 1718,667 r90 top
TP26 "BRAKE_SW" Keystone5002 641,679 r90 top
TP27 "OUTA" Testpoint_Keystone_Compact 3068,3651 r0 top
TP28 "OUTB" Testpoint_Keystone_Compact 2086,3653.31 r180 top
TP29 "OUTC" Testpoint_Keystone_Compact 1071,3651 r180 top
TP30 "EXT_VREG" Keystone5000 3285,1586 r0 top
TP31 "DRVOFF_SW" Keystone5002 641,1105 r0 top
TP32 "DIR_SW" Keystone5002 641,1528 r0 top
TP33 "EXT_SPEED" Keystone5002 1718,464 r90 top
TP39 "SN" Testpoint_Keystone_Miniature 1454.87,1689 r0 top
TP40 "GVDD" Keystone5000 3286,2167 r90 top
TP41 "3V3COM" Keystone5000 3145,1044 r90 top
TP42 "5V_USB" Keystone5000 2705,388 r90 top
TP43 "5V_EXT" Keystone5000 3495,1044 r90 top
TP44 "3V3EXT" Keystone5000 3495,1194 r90 top
TP45 "3V3_MCU" Keystone5000 3145,1194 r90 top
U1 "MCT8329A1IREER" REE0036A-MFG 1995,1718 r180 top
U3 "FT232RNL-REEL" FP-FT232RNL-REEL_SSOP28-MFG 2865.17,717.2 r0 top
U4 "TPD4E004DRYR" DRY0006A 2992,452 r270 top
U5 "MSP430FR2355TPTR" PT0048A-MFG 2278,600 r90 top
Y1 "CSTCR4M00G55B-R0" Murata_CSTCR_G 2349,272 r0 top
ZZ1 "This Assembly Note is for PCB labels only" AssemblyNoteLabel 4176,361 r90 top
ZZ2 "These assemblies are ESD sensitive, ESD precautions shall be observed." AssemblyNote 4026,2829 r90 top
ZZ3 "These assemblies must be clean and free from flux and all contaminants. Use of no clean flux is not acceptable." AssemblyNote 3877,1276 r90 top
ZZ4 "These assemblies must comply with workmanship standards IPC-A-610 Class 2, unless otherwise specified." AssemblyNote 3727,1602 r90 top

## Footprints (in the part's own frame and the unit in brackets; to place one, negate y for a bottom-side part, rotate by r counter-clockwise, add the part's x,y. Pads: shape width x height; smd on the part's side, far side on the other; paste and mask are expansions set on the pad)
0603 [mm] "0603 from SM-752 data"
  rect 1x0.95 smd: 1(-0.8,0) 2(0.8,0)
  silkscreen extent -1.52,-0.69 1.52,0.69, body extent -0.87,-0.47 0.87,0.47, height 1
0603L [mm] "0603 from SM-752 data"
  rect 0.8x0.85 smd: 1(-0.7,0) 2(0.7,0)
  silkscreen extent -0.07,-0.33 0.07,0.33, body extent -0.87,-0.47 0.87,0.47, height 1
0805L [mm] "0805 from SM-752 data"
  rect 1.1x1.4 smd: 1(-0.75,0) 2(0.75,0)
  body extent -1.1,-0.72 1.1,0.72, height 1.45
1206 [mm] "1206 from SM-752 data"
  rect 1.3x1.85 smd: 1(-1.45,0) 2(1.45,0)
  silkscreen extent -2.4,-1.21 2.4,1.21, body extent -1.7,-0.9 1.7,0.9, height 1.35
1206L [mm] "1206 from SM-752 data"
  rect 1.1x1.75 smd: 1(-1.35,0) 2(1.35,0)
  silkscreen extent -0.4,-0.77 0.4,0.77, body extent -1.7,-0.9 1.7,0.9, height 1.35
1210_220L [mm] "1210"
  rect 1.1x2.6 smd: 1(-1.35,0) 2(1.35,0)
  silkscreen extent -0.4,-1.2 0.4,1.2, body extent -1.7,-1.35 1.7,1.35, height 2.2
2220_280L [mm] "Chip Capacitor, Body 5.7x5.0mm, IPC High Density"
  rect 1.4x5.2 smd: 1(-2.5,0) 2(2.5,0)
  silkscreen extent -1.4,-2.5 1.4,2.5, body extent -2.95,-2.6 2.95,2.65, height 2.8
AssemblyNote [mil] "Assembly Note"
AssemblyNoteLabel [mil] "Assembly Note for PCB Labels"
Bourns_3352T [mm] "TH, 3-Leads, Body 9.53x8.89mm, Pitch 2.54mm"
  rect 1.35x1.35 hole 0.85: 1(-2.54,0)
  round 1.35 hole 0.85: 2(0,0) 3(2.54,0)
  silkscreen extent -4.44,-2.6 4.44,7.31, body extent -4.44,-2.21 4.45,7.32, height 3.81
CE_Mark_5mm [mil] "Minimum text height for CE Mark"
  silkscreen extent -138,-98 138,98
CRE2512-R1_R4 [mm] "SMD, 2-Leads, Body 6.45x3.35mm"
  rrect3% 3.1x4 smd: 1(-2.2,0) 2(2.2,0)
  silkscreen extent -0.35,-1.8 0.35,1.8, body extent -3.32,-1.77 3.33,1.78, height 0.9
DQJ0008A [mm] "SMD, 8-Leads, Body 5.75x4.9mm"
  rrect39% 0.91x0.51 smd paste-0.05 mask-0.05: 1(-2.795,1.905) 2(-2.795,0.635) 3(-2.795,-0.635) 4(-2.795,-1.905) 5(2.795,-1.905) 6(2.795,-0.635) 7(2.795,0.635) 8(2.795,1.905)
  rrect8% 1.58x1.25 on Top Paste: 9(-0.38,-1.45) 9(-0.38,0) 9(-0.38,1.45) 9(1.4,-1.45) 9(1.4,0) 9(1.4,1.45)
  rrect3% 3.48x4.47 on Top Solder: 9(0.55,0)
  rrect2% 4.49x4.57 smd paste-2.5 mask-2.5: 9(1.005,0)
  silkscreen extent -3,-2.6 3,2.6, body extent -3.13,-2.45 3.13,2.45, height 1.15
DRY0006A [mm] "USON-6"
  rrect67% 0.45x0.3 smd paste-0.05 mask-0.05: 1(-0.275,0.5)
  rrect67% 0.4x0.3 smd paste-0.05 mask-0.05: 2(-0.3,0) 3(-0.3,-0.5) 4(0.3,-0.5) 5(0.3,0) 6(0.3,0.5)
  body extent -0.5,-0.72 0.5,0.73, height 0.58
FCC_disclaimer [mil]
Fiducial10-20 [mm]
  round 1 smd mask+0.5: 1(0,0)
  Top Layer keep-out circle w1.178: c0,0 r0.5
FP-150060RS75003_0603-MFG [mm]
  rrect13% 0.8x0.8 smd paste+0 mask+0: 1(-0.8,0) 2(0.8,0)
  silkscreen extent -1.88,-0.45 0.03,0.45, body extent -1.3,-0.55 1.3,0.55, height 0.25
FP-691250910002_CONN_TERM_BLK2-MFG [mm]
  rrect4% 2.3x2.3 hole 1.5 paste-2539.97 mask+0: 1(-4.76,1.65)
  round 2.3 hole 1.5 paste-2539.97 mask+0: 2(4.76,1.65)
  silkscreen extent -10.87,-6.3 9.72,6.3, body extent -10.42,-6.4 9.82,6.4, height 0.25
FP-691250910003_CONN_TERM_BLK3-MFG [mm]
  rrect4% 2.3x2.3 hole 1.5 paste-2539.97 mask+0: 1(-9.52,1.65)
  round 2.3 hole 1.5 paste-2539.97 mask+0: 2(0,1.65) 3(9.52,1.65)
  silkscreen extent -15.08,-6.3 14.48,6.3, body extent -15.18,-6.4 14.58,6.4, height 0.25
FP-885012206120_0603-MFG [mm]
  rrect13% 0.8x0.8 smd paste+0 mask+0: 1(-0.75,0) 2(0.75,0)
  silkscreen extent -0.85,-0.77 0.85,0.77, body extent -1.25,-0.55 1.25,0.55, height 0.25
FP-FT232RNL-REEL_SSOP28-MFG [mm]
  rrect25% 2x0.4 smd paste+0 mask+0: 1(-3.5,4.225)
  rrect100% 2x0.4 smd paste+0 mask+0: 2(-3.5,3.575) 3(-3.5,2.925) 4(-3.5,2.275) 5(-3.5,1.625) 6(-3.5,0.975) 7(-3.5,0.325) 8(-3.5,-0.325) 9(-3.5,-0.975) 10(-3.5,-1.625) 11(-3.5,-2.275) 12(-3.5,-2.925) 13(-3.5,-3.575) 14(-3.5,-4.225) 15(3.5,-4.225) 16(3.5,-3.575) 17(3.5,-2.925) 18(3.5,-2.275) 19(3.5,-1.625) 20(3.5,-0.975) 21(3.5,-0.325) 22(3.5,0.325) 23(3.5,0.975) 24(3.5,1.625) 25(3.5,2.275) 26(3.5,2.925) 27(3.5,3.575) 28(3.5,4.225)
  silkscreen extent -5.17,-5.2 2,5.2, body extent -4.6,-5.3 4.6,5.3, height 0.25
Harwin_D3082-05 [mm] "Shorting Plug, 10.16mm spacing, TH"
  round 1.8 hole 1.3: 1(-5.08,0) 2(5.08,0)
  silkscreen extent -3.9,-0.53 3.9,0.53, body extent -5.6,-0.52 5.61,0.52, height 6.63
IEC_HotSurface_Small [mil]
  silkscreen extent -107,-93 107,92
Keystone5000 [mil] "For Keystone 500x miniature loop terminals"
  round 80 hole 40: 1(0,0)
  silkscreen extent -52,-52 52,52, body extent -49,-49 49,49, height 182
Keystone5001#1 [mm] "For Keystone 500x miniature loop terminals"
  round 1.35 hole 0.85 paste-2539.97: 1(0,0)
  silkscreen extent -1.33,-1.33 1.33,1.33, body extent -1.24,-1.24 1.25,1.25, height 4.62
Keystone5001#2 [mm] "For Keystone 500x miniature loop terminals"
  round 2.032 hole 1.016: 1(0,0)
  silkscreen extent -1.33,-1.33 1.33,1.33, body extent -1.24,-1.24 1.25,1.25, height 4.62
Keystone5002 [mil] "For Keystone 500x miniature loop terminals"
  round 80 hole 40: 1(0,0)
  silkscreen extent -52,-52 52,52, body extent -49,-49 49,49, height 182
Keystone_1902E [mil] "Hex Standoff, 4-40 threaded, nylon"
  round 1 on Mech4: 0(0,0)
  body extent -145,-126 146,126, height 1001
KTT0002A-MFG#1 [mm]
  rrect10% 1.05x3.82 smd paste+0 mask+0: 1(-2.54,-7.755) 3(2.54,-7.755)
  rrect1% 8.55x7.48 smd paste-1000 mask+0: 4(0,2.545)
  silkscreen extent -5.13,-4.62 5.13,4.62, body extent -5.23,-9.76 5.23,6.39, height 0.25
KTT0002A-MFG#2 [mm]
  rrect10% 1.05x3.82 smd paste+0 mask+0: 1(-2.54,-7.755) 3(2.54,-7.755)
  rrect1% 8.55x7.48 smd paste-1000 mask+0.05: 4(0,2.545)
  silkscreen extent -5.13,-4.62 5.13,4.62, body extent -5.23,-9.76 5.23,6.39, height 0.25
KYB_1250x3500 [mm] "TH, 2-Leads, Dia 12.5mm, Lead Spacing 5mm"
  rect 1.35x1.35 hole 0.85: 1(-2.5,0)
  round 1.35 hole 0.85: 2(2.5,0)
  silkscreen extent -8,-6.5 6.5,6.5, body extent -6.5,-6.5 6.51,6.5, height 36.51
Molex_1051640001 [mm] "Receptacle, USB 2.0, Micro B, 5 Pos, 0.65mm Pitch, R/A, SMT"
  rrect22% 0.45x1.38 smd: 1(1.3,4.11) 2(0.65,4.11) 3(0,4.11) 4(-0.65,4.11) 5(-1.3,4.11)
  rrect7% 1.475x2.1 smd: 6(-2.462,3.75) 11(2.462,3.75)
  rrect100% 1.4x2.1 hole 0.6 slot 1.3 at 90 deg: 7(-3.95,1.45) 10(3.95,1.45)
  rrect7% 1.375x1.9 smd: 8(-0.937,1.45) 9(0.937,1.45)
  silkscreen extent 1.2,5.1 1.4,5.4, body extent -4.1,-0.7 4.1,4.47, height 2.45
Murata_CSTCR_G [mm] "Murata"
  rect 0.4x2.6 smd: 1(-1.5,0) 2(0,0) 3(1.5,0)
  Top Layer region: -0.4,0.8 0.4,0.8 0.4,1.3 -0.4,1.3
  Top Layer region: -0.4,-1.301 -0.4,-0.801 0.4,-0.801 0.4,-1.301
  Top Layer region: -1.9,0.8 -1.1,0.8 -1.1,1.3 -1.9,1.3
  Top Layer region: -1.9,-1.301 -1.9,-0.801 -1.1,-0.801 -1.1,-1.301
  Top Layer region: 1.1,0.8 1.9,0.8 1.9,1.3 1.1,1.3
  Top Layer region: 1.1,-1.301 1.1,-0.801 1.9,-0.801 1.9,-1.301
  body extent -2.25,-1 2.25,1, height 1.16
Net-Tie_0805_HV_NoOverlay [mil] "0805_HV pads tied by 10mil copper trace which can be cut.  An 0805 part can be placed on pads."
  rect 50x63 smd paste-25: 1(-40,0) 2(40,0)
  Top Layer lines w10: -16,0 16,0
  Top Layer keep-out lines w1: -22,30.91 -22,-30.91 ; -14.96,30.91 14.96,30.91 ; 22,30.91 22,-30.91 ; -14.96,-30.91 14.96,-30.91
"NY PMS 440 0025 PH" [mm] "4-40 nylon screw and mounting hole"
  round 8 hole 3.2: 1(0,0)
  body extent -3.31,-3.3 3.3,3.3, height 2.69
PT0048A-MFG [mm]
  rrect33% 1.4x0.3 smd paste-1000 mask+0: 1(-4.25,2.75) 2(-4.25,2.25) 3(-4.25,1.75) 4(-4.25,1.25) 5(-4.25,0.75) 6(-4.25,0.25) 7(-4.25,-0.25) 8(-4.25,-0.75) 9(-4.25,-1.25) 10(-4.25,-1.75) 11(-4.25,-2.25) 12(-4.25,-2.75) 25(4.25,-2.75) 26(4.25,-2.25) 27(4.25,-1.75) 28(4.25,-1.25) 29(4.25,-0.75) 30(4.25,-0.25) 31(4.25,0.25) 32(4.25,0.75) 33(4.25,1.25) 34(4.25,1.75) 35(4.25,2.25) 36(4.25,2.75)
  rrect33% 0.3x1.4 smd paste-1000 mask+0: 13(-2.75,-4.25) 14(-2.25,-4.25) 15(-1.75,-4.25) 16(-1.25,-4.25) 17(-0.75,-4.25) 18(-0.25,-4.25) 19(0.25,-4.25) 20(0.75,-4.25) 21(1.25,-4.25) 22(1.75,-4.25) 23(2.25,-4.25) 24(2.75,-4.25) 37(2.75,4.25) 38(2.25,4.25) 39(1.75,4.25) 40(1.25,4.25) 41(0.75,4.25) 42(0.25,4.25) 43(-0.25,4.25) 44(-0.75,4.25) 45(-1.25,4.25) 46(-1.75,4.25) 47(-2.25,4.25) 48(-2.75,4.25)
  silkscreen extent -5.65,-3.6 3.6,3.6, body extent -5.05,-5.05 5.05,5.05, height 0.25
REE0036A-MFG [mm]
  rrect50% 0.6x0.2 smd paste+0 mask+0: 1(-1.9,1.8) 2(-1.9,1.4) 3(-1.9,1) 4(-1.9,0.6) 5(-1.9,0.2) 6(-1.9,-0.2) 7(-1.9,-0.6) 8(-1.9,-1) 9(-1.9,-1.4) 10(-1.9,-1.8) 19(1.9,-1.8) 20(1.9,-1.4) 21(1.9,-1) 22(1.9,-0.6) 23(1.9,-0.2) 24(1.9,0.2) 25(1.9,0.6) 26(1.9,1) 27(1.9,1.4) 28(1.9,1.8)
  rrect50% 0.2x0.6 smd paste+0 mask+0: 11(-1.4,-2.4) 12(-1,-2.4) 13(-0.6,-2.4) 14(-0.2,-2.4) 15(0.2,-2.4) 16(0.6,-2.4) 17(1,-2.4) 18(1.4,-2.4) 29(1.4,2.4) 30(1,2.4) 31(0.6,2.4) 32(0.2,2.4) 33(-0.2,2.4) 34(-0.6,2.4) 35(-1,2.4) 36(-1.4,2.4)
  rrect7% 2.7x3.7 smd paste-1000 mask+0: 37(0,0)
  silkscreen extent -2.88,-2.55 2.05,2.55, body extent -2.3,-2.8 2.3,2.8, height 0.25
SOD-323 [mm] "NXP recommended land pattern"
  rect 0.6x0.6 smd paste-0.05: 1(-1.1,0) 2(1.1,0)
  silkscreen extent -2.06,-0.86 1.53,0.86, body extent -1.3,-0.67 1.3,0.68, height 1.1
SW_434121025816 [mm] "SMD, 2-Leads, Body 6x3.9mm, Pitch 6.5mm"
  rect 1.5x1.4 smd: 1(-3.25,0) 2(3.25,0)
  silkscreen extent -3,-1.95 3,1.95, body extent -3.65,-1.95 3.65,1.95, height 2.5
SW_B12AP [mm] "NKK Switches"
  rect 1.35x1.35 hole 0.85 paste-2539.97: 1(-1,2.54)
  round 1.35 hole 0.85 paste-2539.97: 2(-1,0) 3(-1,-2.54)
  silkscreen extent -4.27,-4.4 3.4,4.4, body extent -3.4,-4.39 3.4,4.39, height 22.87
SW_G2xAP [mm] "TH, 6-Leads, Body 4.5x7mm, Pitch 2.54mm"
  rect 1.1x1.1 hole 0.6: 1(-2.54,1.27)
  round 1.1 hole 0.6: 2(0,1.27) 3(2.54,1.27) 4(-2.54,-1.27) 5(0,-1.27) 6(2.54,-1.27)
  silkscreen extent -3.51,-2.25 3.5,2.6, body extent -3.51,-2.25 3.51,2.25, height 10.76
Testpoint_Keystone_Compact [mil] "Compact SMT test point"
  rect 185x135 smd: 1(0,0)
  silkscreen extent -110,-80 110,80, body extent -75,-56 75,56, height 91
Testpoint_Keystone_Miniature [mil] "Miniature SMT test point"
  rect 135x70 smd: 1(0,0)
  silkscreen extent -78,-46 78,45, body extent -52,-20 52,20, height 61
TI_Stacked_Overlay_Small [mil]
  silkscreen extent -418,-98 418,98
TSW-114-07-G-S [mm] "Samtec 100mil, 1x14, 230 mil above insulator"
  rrect6% 1.65x1.65 hole 1.016: 1(-16.51,0)
  round 1.65 hole 1.016: 2(-13.97,0) 3(-11.43,0) 4(-8.89,0) 5(-6.35,0) 6(-3.81,0) 7(-1.27,0) 8(1.27,0) 9(3.81,0) 10(6.35,0) 11(8.89,0) 12(11.43,0) 13(13.97,0) 14(16.51,0)
  silkscreen extent -17.78,-1.27 17.78,1.65, body extent -17.78,-1.27 17.78,1.27, height 8.38
TSW-116-07-G-D [mm] "Samtec 100mil, 2x16, 230 mil above insulator"
  rrect6% 1.65x1.65 hole 1.016: 1(-19.05,-1.27)
  round 1.65 hole 1.016: 2(-19.05,1.27) 3(-16.51,-1.27) 4(-16.51,1.27) 5(-13.97,-1.27) 6(-13.97,1.27) 7(-11.43,-1.27) 8(-11.43,1.27) 9(-8.89,-1.27) 10(-8.89,1.27) 11(-6.35,-1.27) 12(-6.35,1.27) 13(-3.81,-1.27) 14(-3.81,1.27) 15(-1.27,-1.27) 16(-1.27,1.27) 17(1.27,-1.27) 18(1.27,1.27) 19(3.81,-1.27) 20(3.81,1.27) 21(6.35,-1.27) 22(6.35,1.27) 23(8.89,-1.27) 24(8.89,1.27) 25(11.43,-1.27) 26(11.43,1.27) 27(13.97,-1.27) 28(13.97,1.27) 29(16.51,-1.27) 30(16.51,1.27) 31(19.05,-1.27) 32(19.05,1.27)
  silkscreen extent -21.35,-2.54 20.32,2.54, body extent -20.32,-2.54 20.32,2.54, height 8.38
WCAP-ASLI_D6.3H7.7 [mm] "Aluminium Electrolytic V-Chip SMT Capacitors, 6.3x7.7mm"
  rect 3.5x1.6 smd: 1(2.8,0) 2(-2.8,0)
  silkscreen extent -3.4,-3.4 3.4,3.4, body extent -3.65,-3.3 3.65,3.3, height 7.7
WCAP-CSGP_0603_L1.6W0.8H0.8_Reflow [mm] "Ceramic Capacitors, body 1.6x0.8mm"
  rect 0.8x0.8 smd: 1(-0.75,0) 2(0.75,0)
  body extent -0.8,-0.4 0.8,0.4, height 0.8
WCAP-CSGP_0805_L2W1.25H0.8_Reflow [mm] "Ceramic Capacitors, body 2x1.25mm"
  rect 0.9x1.3 smd: 1(-0.95,0) 2(0.95,0)
  body extent -1,-0.62 1,0.63, height 0.8
WCAP-CSGP_0805_L2W1.25H1.25 [mm] "Ceramic Capacitors, body 2x1.25mm"
  rect 0.9x1.3 smd: 1(-0.95,0) 2(0.95,0)
  body extent -1,-0.63 1,0.63, height 1.25
WEEE_Minimum [mil] "WEEElie bin"
  silkscreen extent -95,-172 99,104
WL-SMCW_Green_0805 [mm] "SMD, 2-Leads, Body 2x1.25mm"
  rect 1.1x1.2 smd: 1(-1.05,0) 2(1.05,0)
  silkscreen extent -2.4,-1.1 1.5,1.1, body extent -1,-0.62 1,0.63, height 0.7
WL-SMCW_RED_0805 [mm] "SMD, 2-Leads, Body 1.6x0.8mm"
  rect 1.1x1.2 smd: 1(-1.05,0) 2(1.05,0)
  silkscreen extent -2.4,-1.1 1.5,1.1, body extent -1,-0.62 1,0.63, height 0.7
Wurth_60900213421 [mil] "Shunt, 2.54mm, Black"
  round 1 on Mech3: 0(0,0)
  body extent -98,-48 98,48, height 338
WURTH_61300211121 [mm] "Header, 2.54mm, 2x1, TH"
  rrect50% 1.65x1.65 hole 1.15: 1(-1.27,0)
  round 1.65 hole 1.15: 2(1.27,0)
  body extent -2.54,-1.27 2.54,1.27, height 8.54
WURTH_61300311121 [mm] "Header, 2.54mm, 3x1, TH"
  rrect50% 1.65x1.65 hole 1.15: 1(-2.54,0)
  round 1.65 hole 1.15: 2(0,0) 3(2.54,0)
  body extent -3.81,-1.27 3.81,1.27, height 8.54
WURTH_61300411121 [mm] "Header, 2.54mm, 4x1, TH"
  rrect50% 1.65x1.65 hole 1.15: 1(-3.81,0)
  round 1.65 hole 1.15: 2(-1.27,0) 3(1.27,0) 4(3.81,0)
  body extent -5.08,-1.27 5.08,1.27, height 8.54
Wurth_61300621121 [mm] "Header, 2.54mm, 3x2, TH"
  rect 1.6x1.6 hole 1.1: 1(-1.27,2.54)
  round 1.6 hole 1.1: 2(1.27,2.54) 3(-1.27,0) 4(1.27,0) 5(-1.27,-2.54) 6(1.27,-2.54)
  silkscreen extent -2.8,-3.82 2.54,3.8, body extent -2.54,-3.82 2.54,3.8, height 7.27

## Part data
C1: library part CMP-0108062-1, "WCAP-CSGP Multilayer Ceramic Chip Capacitor, General Purpose, size 0603, X5R, 10µF, 6.3VDC", Capacitance Tolerance=+/-20%, Case/Size Code=0603, Insulation Resistance=0.01GOhm, Manufacturer="Wurth Elektronik", Operating Temperature Max=85°C, Operating Temperature Min=-55°C, Rated Voltage (DC)=6.3V
C2 C38: library part CMP-0064931-4, "CAP, CERM, 0.1 uF, 10 V,+/- 10%, X7R, 0603", Cap_Case=0603, Manufacturer="Wurth Elektronik", Supplier Part Number 1=732-7939-1-ND, TempCo=X7R, Tolerance_%=10%, Value1=Unknown, Value2=10V, ValueDisplayed=0.1uF
C3: library part CMP-0115615-1, "WCAP-CSGP Multilayer Ceramic Chip Capacitor, General Purpose, size 0805, X7R Class II, 470nF, 100VDC", Capacitance Tolerance=+/-10%, Case/Size Code=0805, Insulation Resistance=0.2GOhm, Manufacturer="Wurth Elektronik", Operating Temperature Max=125°C, Operating Temperature Min=-55°C, Rated Voltage (DC)=100V
C4: library part CMP-0111654-1, "WCAP-CSGP Multilayer Ceramic Chip Capacitor, General Purpose, size 0603, X5R, 1µF, 6.3VDC", Capacitance Tolerance=+/-20%, Case/Size Code=0603, Insulation Resistance=0.1GOhm, Manufacturer="Wurth Elektronik", Operating Temperature Max=85°C, Operating Temperature Min=-55°C, Rated Voltage (DC)=6.3V
C5: library part CMP-0111676-1, "WCAP-CSGP Multilayer Ceramic Chip Capacitor, General Purpose, size 0603, X5R, 10µF, 25VDC", Capacitance Tolerance=+/20%, Insulation Resistance=0.01GOhm, Manufacturer="Wurth Elektronik", Operating Temperature Max=85°C, Operating Temperature Min=-55°C, Rated Voltage (DC)=25V
C6: library part CMP-0009304-2, "CAP, CERM, 10 uF, 100 V, +/- 20%, X7R, 2220", Cap_Case=2220, Manufacturer=AVX, Supplier Part Number 1=478-9622-1-ND, TempCo=X7R, Tolerance_%=20%, Value1=Unknown, Value2=100V, ValueDisplayed=10uF
C7 C11 C16 C47: library part CMP-0097294-1, "0.1 µF ±10% 100V Ceramic Capacitor X7R 0603 (1608 Metric)", Digikey Part Number=732-885012206120TR-ND, Manufacturer="Wurth Electronics", Mouser Part Number=710-885012206120, Operating Temperature Range="-55°C to +125°C", TempCo=15%, Temperature Characteristic=X7R, Tolerance_%=10%, ValueDisplayed=100nF
C8 C9 C10: library part CMP-0104504-1, "WCAP-CSGP Multilayer Ceramic Chip Capacitor, General Purpose, size 0603, X5R, 1µF, 25VDC", Capacitance Tolerance=+/-20%, Case/Size Code=0603, Insulation Resistance=0.5GOhm, Manufacturer="Wurth Elektronik", Operating Temperature Max=85°C, Operating Temperature Min=-55°C, Rated Voltage (DC)=25V
C12 C13 C14 C24 C25 C26: library part CMP-0008756-2, "CAP CER 3900PF 100V X7R 1206", Cap_Case=1206, Manufacturer="AVX Corporation", Supplier Part Number 1=478-6364-1-ND, TempCo=X7R, Tolerance_%=10%, Value1=Unknown, Value2=100V, ValueDisplayed=3900pF
C15 C17 C19 C27 C28 C29: library part CMP-0007441-5, "CAP, CERM, 2000 pF, 50 V, +/- 10%, X7R, 0603", Cap_Case=0603, Manufacturer=MuRata, TempCo=X7R, Tolerance_%=10%, Value1=Unknown, Value2=50V, ValueDisplayed=2000pF
C18 C20 C44: library part CMP-0009182-2, "CAP, CERM, 4.7 uF, 100 V, +/- 10%, X7S, 1210", Cap_Case=1210, Manufacturer=MuRata, Supplier Part Number 1=81-GRM32DC72A475KE1L, TempCo=X7S, Tolerance_%=10%, Value1=Unknown, Value2=100V, ValueDisplayed=4.7uF
C21 C22 C23: library part CMP-0108439-1, "WCAP-CSGP Multilayer Ceramic Chip Capacitor, General Purpose, size 0805, X7R, 10nF, 100VDC", Capacitance Tolerance=+/-10%, Case/Size Code=0805, Insulation Resistance=10GOhm, Manufacturer="Wurth Elektronik", Operating Temperature Max=125°C, Operating Temperature Min=-55°C, Rated Voltage (DC)=100V
C30 C32: library part CMP-0006740-4, "CAP, CERM, 330 pF, 100 V, +/- 10%, X7R, 0603", Cap_Case=0603, Manufacturer=AVX, Supplier Part Number 1=478-1196-1-ND, TempCo=X7R, Tolerance_%=10%, Value1="0.472 ohm", Value2=100V, ValueDisplayed=330pF
C31: library part CMP-0006998-4, "CAP, CERM, 0.01 uF, 50 V, +/- 5%, C0G/NP0, 0603", Cap_Case=0603, Manufacturer=TDK, Supplier Part Number 1=445-14056-1-ND, TempCo=C0G/NP0, Tolerance_%=5%, Value1=Unknown, Value2=50V, ValueDisplayed=0.01uF
C33: library part CMP-0110675-1, "WCAP-ASLI Aluminum Electrolytic Capacitor, V-Chip, D6.3 x H7.7mm, 10uF, 80V", Capacitance Tolerance=+/-20%, Leakage Current=8uA, Manufacturer="Wurth Elektronik", Operating Temperature Max=105°C, Operating Temperature Min=-55°C, Rated Voltage (DC)=80V, Ripple Current=35mA
C34 C35: library part CMP-0009875-2, "CAP, AL, 390 uF, 100 V, +/- 20%, 0.026 ohm, TH", Cap_Case=12.5x35mm, Manufacturer=Chemi-Con, Supplier Part Number 1=565-4021-ND, Tolerance_%=20%, Value1="0.026 ohm", Value2=100V, ValueDisplayed=390uF
C36: library part CMP-0104643-1, "WCAP-CSGP Multilayer Ceramic Chip Capacitor, General Purpose, size 0603, X7R, 100pF, 10VDC", Capacitance Tolerance=+/-10%, Case/Size Code=0603, Insulation Resistance=10GOhm, Manufacturer="Wurth Elektronik", Operating Temperature Max=125°C, Operating Temperature Min=-55°C, Rated Voltage (DC)=10V
C37: library part CMP-0108062-1, "WCAP-CSGP Multilayer Ceramic Chip Capacitor, General Purpose, size 0603, X5R, 10µF, 6.3VDC", Capacitance Tolerance=+/-20%, Insulation Resistance=0.01GOhm, Manufacturer="Wurth Elektronik", Operating Temperature Max=85°C, Operating Temperature Min=-55°C, Rated Voltage (DC)=6.3V
C39: library part CMP-0082630-1, "CAP, CERM, 2000 pF, 50 V,+/- 5%, C0G/NP0, 1206", Cap_Case=1206, Manufacturer=AVX, Supplier Part Number 1=478-6053-1-ND, TempCo=C0G/NP0, Tolerance_%=5%, Value2=50V, ValueDisplayed=2000pF
C46: library part CMP-0007498-4, "CAP, CERM, 4.7 uF, 10 V, +/- 20%, X7R, 0603", Cap_Case=0603, Manufacturer=MuRata, TempCo=X7R, Tolerance_%=20%, Value1=Unknown, Value2=10V, ValueDisplayed=4.7uF
C48: library part CMP-0006826-4, "CAP, CERM, 1000 pF, 16 V, +/- 10%, X7R, 0603", Cap_Case=0603, Manufacturer="Wurth Elektronik", Supplier Part Number 1=710-885012206034, TempCo=X7R, Tolerance_%=10%, Value1=Unknown, Value2=16V, ValueDisplayed=1000pF
C49: library part CMP-0007696-2, "CAP, CERM, 1 uF, 50 V, +/- 10%, X7R, 0805", Cap_Case=0805, Manufacturer="Wurth Elektronik", Supplier Part Number 1=710-885012207103, TempCo=X7R, Tolerance_%=10%, Value1=Unknown, Value2=50V, ValueDisplayed=1uF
